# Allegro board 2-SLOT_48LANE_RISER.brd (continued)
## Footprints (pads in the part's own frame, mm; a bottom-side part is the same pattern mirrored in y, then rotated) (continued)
PCIE_X16D_H11
  round 2.413 hole 2.413 unplated: (-1.25,-11.65) (-1.25,-84.8)
  rect 1.194x1.194 hole 0.711: A1(0,0)
  round 1.194 hole 0.711: A2(2,-1) A3(0,-2) A4(2,-3) A5(0,-4) A6(2,-5) A7(0,-6) A8(2,-7) A9(0,-8) A10(2,-9) A11(0,-10) A12(2,-13) A13(0,-14) A14(2,-15) A15(0,-16) A16(2,-17) A17(0,-18) A18(2,-19) A19(0,-20) A20(2,-21) A21(0,-22) A22(2,-23) A23(0,-24) A24(2,-25) A25(0,-26) A26(2,-27) A27(0,-28) A28(2,-29) A29(0,-30) A30(2,-31) A31(0,-32) A32(2,-33) A33(0,-34) A34(2,-35) A35(0,-36) A36(2,-37) A37(0,-38) A38(2,-39) A39(0,-40) A40(2,-41) A41(0,-42) A42(2,-43) A43(0,-44) A44(2,-45) A45(0,-46) A46(2,-47) A47(0,-48) A48(2,-49) A49(0,-50) A50(2,-51) A51(0,-52) A52(2,-53) A53(0,-54) A54(2,-55) A55(0,-56) A56(2,-57) A57(0,-58) A58(2,-59) A59(0,-60) A60(2,-61) A61(0,-62) A62(2,-63) A63(0,-64) A64(2,-65) A65(0,-66) A66(2,-67) A67(0,-68) A68(2,-69) A69(0,-70) A70(2,-71) A71(0,-72) A72(2,-73) A73(0,-74) A74(2,-75) A75(0,-76) A76(2,-77) A77(0,-78) A78(2,-79) A79(0,-80) A80(2,-81) A81(0,-82) A82(2,-83) B1(-2.5,0) B2(-4.5,-1) B3(-2.5,-2) B4(-4.5,-3) B5(-2.5,-4) B6(-4.5,-5) B7(-2.5,-6) B8(-4.5,-7) B9(-2.5,-8) B10(-4.5,-9) B11(-2.5,-10) B12(-4.5,-13) B13(-2.5,-14) B14(-4.5,-15) B15(-2.5,-16) B16(-4.5,-17) B17(-2.5,-18) B18(-4.5,-19) B19(-2.5,-20) B20(-4.5,-21) B21(-2.5,-22) B22(-4.5,-23) B23(-2.5,-24) B24(-4.5,-25) B25(-2.5,-26) B26(-4.5,-27) B27(-2.5,-28) B28(-4.5,-29) B29(-2.5,-30) B30(-4.5,-31) B31(-2.5,-32) B32(-4.5,-33) B33(-2.5,-34) B34(-4.5,-35) B35(-2.5,-36) B36(-4.5,-37) B37(-2.5,-38) B38(-4.5,-39) B39(-2.5,-40) B40(-4.5,-41) B41(-2.5,-42) B42(-4.5,-43) B43(-2.5,-44) B44(-4.5,-45) B45(-2.5,-46) B46(-4.5,-47) B47(-2.5,-48) B48(-4.5,-49) B49(-2.5,-50) B50(-4.5,-51) B51(-2.5,-52) B52(-4.5,-53) B53(-2.5,-54) B54(-4.5,-55) B55(-2.5,-56) B56(-4.5,-57) B57(-2.5,-58) B58(-4.5,-59) B59(-2.5,-60) B60(-4.5,-61) B61(-2.5,-62) B62(-4.5,-63) B63(-2.5,-64) B64(-4.5,-65) B65(-2.5,-66) B66(-4.5,-67) B67(-2.5,-68) B68(-4.5,-69) B69(-2.5,-70) B70(-4.5,-71) B71(-2.5,-72) B72(-4.5,-73) B73(-2.5,-74) B74(-4.5,-75) B75(-2.5,-76) B76(-4.5,-77) B77(-2.5,-78) B78(-4.5,-79) B79(-2.5,-80) B80(-4.5,-81) B81(-2.5,-82) B82(-4.5,-83)
PQFN16_IR3823
  rect 0.305x0.66 smd: 1(-1.25,-1.78) 2(-0.75,-1.78) 3(-0.25,-1.78) 4(0.25,-1.78) 5(0.75,-1.78) 6(1.25,-1.78)
  rect 0.66x0.305 smd: 7(1.7,-1.03) 8(1.7,-0.53) 9(1.7,-0.03) 13(-1.7,-0.03) 14(-1.7,-0.53) 15(-1.7,-1.03)
  rect 0.787x1.067 smd: 10(1.69,0.92)
  rect 1.524x1.626 smd: 11(0.195,1.2)
  rect 1.321x1.626 smd: 12(-1.44,1.2)
  rect 2.438x1.422 smd: 16(0,-0.53)
PQFN17_IR3895
  rect 0.305x0.711 smd: 1(-1.95,-3.15) 2(-1.3,-3.15) 3(-0.65,-3.15) 4(0,-3.15) 5(0.65,-3.15) 6(1.3,-3.15) 7(1.95,-3.15)
  rect 0.711x0.305 smd: 8(2.45,-2.32) 9(2.45,-1.67) 10(2.45,-1.02) 14(-2.45,-1.02) 15(-2.45,-1.67) 16(-2.45,-2.32)
  custom 0.263x0.263 smd: 11(2.5,1.16)
  custom 0.533x0.533 smd: 12(0.28,2.76)
  custom 0.405x0.405 smd: 13(-2.5,1.16)
  rect 2.692x1.549 smd: 17(0,-1.66)
PQFN17_IR3899
  rect 0.254x0.762 smd: 1(-1.5,-2.425) 2(-1,-2.425) 3(-0.5,-2.425) 4(0,-2.425) 5(0.5,-2.425) 6(1,-2.425) 7(1.5,-2.425)
  rect 0.762x0.254 smd: 8(1.925,-1.645) 9(1.925,-1.145) 10(1.925,-0.645) 14(-1.925,-0.645) 15(-1.925,-1.145) 16(-1.925,-1.645)
  custom 0.2x0.2 smd: 11(1.695,1.205)
  custom 0.405x0.405 smd: 12(0.285,1.395)
  custom 0.343x0.343 smd: 13(-1.615,1.205)
  rect 2.184x1.194 smd: 17(0,-1.145)
PWR2X6D2NH_P3W3H8-9_RA
  round 3.023 hole 3.023 unplated: (-12.85,-4.32) (-2.15,-4.32)
  rect 1.549x1.549 hole 1.041: 1(0,0)
  round 1.549 hole 1.041: 2(-3,0) 3(-6,0) 4(-9,0) 5(-12,0) 6(-15,0) 7(0,3) 8(-3,3) 9(-6,3) 10(-9,3) 11(-12,3) 12(-15,3)
R0402
  rect 0.457x0.508 smd: 1(-0.4,0) 2(0.4,0)
R0603
  rect 0.813x0.711 smd: 1(-0.737,0) 2(0.737,0)
SC70-5XB
  rect 0.914x0.406 smd: 1(-1.1,0.65) 2(-1.1,0) 3(-1.1,-0.65) 4(1.1,-0.65) 5(1.1,0.65)
SOIC8
  rect 1.727x0.559 smd: 1(-2.642,1.905) 2(-2.642,0.635) 3(-2.642,-0.635) 4(-2.642,-1.905) 5(2.642,-1.905) 6(2.642,-0.635) 7(2.642,0.635) 8(2.642,1.905)
SOT23
  rect 0.914x0.813 smd: 1(-1,0.95) 2(-1,-0.95) 3(1,0)
SOT23_GDS
  rect 1.422x1.016 smd: D(1.1,0) G(-1.1,0.95) S(-1.1,-0.95)
TAJ_D_7-3X4-3
  rect 2.388x2.438 smd: 1(-3.12,0) 2(3.12,0)
TSSOP8_D65_1D2
  rect 1.168x0.61 smd: 1(-2.175,1.05) 4(-2.175,-1.05) 5(2.175,-1.05) 8(2.175,1.05)
  rect 1.168x0.432 smd: 2(-2.175,0.325) 3(-2.175,-0.325) 6(2.175,-0.325) 7(2.175,0.325)
TSSOP24_P0-65W5-6H1-2
  rect 1.6x0.305 smd: 1(-2.8,3.575) 2(-2.8,2.925) 3(-2.8,2.275) 4(-2.8,1.625) 5(-2.8,0.975) 6(-2.8,0.325) 7(-2.8,-0.325) 8(-2.8,-0.975) 9(-2.8,-1.625) 10(-2.8,-2.275) 11(-2.8,-2.925) 12(-2.8,-3.575) 13(2.8,-3.575) 14(2.8,-2.925) 15(2.8,-2.275) 16(2.8,-1.625) 17(2.8,-0.975) 18(2.8,-0.325) 19(2.8,0.325) 20(2.8,0.975) 21(2.8,1.625) 22(2.8,2.275) 23(2.8,2.925) 24(2.8,3.575)
unnamed
  round 0.991 smd: 1(0,0)
VFQFPN40_P0-4_EPAD
  custom 0.044x0.044 smd: 1(-2.45,1.8) 2(-2.45,1.4) 3(-2.45,1) 4(-2.45,0.6) 5(-2.45,0.2) 6(-2.45,-0.2) 7(-2.45,-0.6) 8(-2.45,-1) 9(-2.45,-1.4) 10(-2.45,-1.8) 11(-1.8,-2.45) 12(-1.4,-2.45) 13(-1,-2.45) 14(-0.6,-2.45) 15(-0.2,-2.45) 16(0.2,-2.45) 17(0.6,-2.45) 18(1,-2.45) 19(1.4,-2.45) 20(1.8,-2.45) 21(2.45,-1.8) 22(2.45,-1.4) 23(2.45,-1) 24(2.45,-0.6) 25(2.45,-0.2) 26(2.45,0.2) 27(2.45,0.6) 28(2.45,1) 29(2.45,1.4) 30(2.45,1.8) 31(1.8,2.45) 32(1.4,2.45) 33(1,2.45) 34(0.6,2.45) 35(0.2,2.45) 36(-0.2,2.45) 37(-0.6,2.45) 38(-1,2.45) 39(-1.4,2.45) 40(-1.8,2.45)
  rect 3.607x3.607 smd: 41(0,0)
X2QFN10_0-5_2X1-5
  rect 0.584x0.305 smd: 1(-0.638,0.75) 4(-0.638,-0.75) 6(0.638,-0.75) 9(0.638,0.75)
  rect 0.584x0.254 smd: 2(-0.638,0.25) 3(-0.638,-0.25) 7(0.638,-0.25) 8(0.638,0.25)
  rect 0.279x0.635 smd: 5(0,-0.86) 10(0,0.86)

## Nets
GND: C1.2(B) C2.2(B) C3.2(B) C4.2(B) C5.2(B) C6.2(B) C7.2(B) C8.2(B) C9.2(B) C10.2(B) C11.2(B) C12.2(B) C13.2(B) C14.2(B) C15.2(B) C16.2(B) C17.2(B) C18.2(B) C19.2(B) C20.2(B) C21.2(B) C22.2(B) C47.2(B) C48.2(B) C49.2(B) C50.2(B) C51.2(B) C52.2(B) C53.2(B) C54.2(B) C127.2(B) C128.2(B) C129.2(B) C130.2(B) C131.2(B) C132.2(B) C133.2(B) C134.2(B) C135.2(B) C136.2(B) C137.2(B) C138.2(B) C139.2(B) C140.2(B) C141.2(B) C142.2(B) C143.2(B) C144.2(B) C145.2(B) C146.2(B) C147.2(B) C148.2(B) C149.2(B) C150.2(B) C151.2(B) C152.2(B) C153.2(B) C154.2(B) C155.2(B) C156.2(B) C160.2(B) C161.2(B) C162.2(B) C163.2(B) C164.2(B) C165.2(B) C166.2(B) C167.2(B) C170.2(B) C171.2(B) C173.2(B) C174.2(B) C175.2(B) C176.2(B) C177.2(B) C178.2(B) C179.2(B) C180.2(B) C181.2(B) C182.2(B) C183.2(B) C184.2(B) C185.2(B) C186.2(B) C187.2(B) C188.2(B) C194.2(B) C215.2(B) C216.2(B) C217.2(B) C218.2(B) C219.2(B) C220.2(B) C221.2(B) C222.2(B) C223.2(B) C224.2(B) C225.2(B) C226.2(B) C227.2(B) C242.2(B) C243.2(B) C244.2(B) C245.2(B) C246.2(B) C247.2(B) C248.2(B) C249.2(B) C250.2(B) C251.2(B) C252.2(B) C253.2(B) C254.2(B) C255.2(B) C257.2(B) C258.2(B) C259.2(B) C265.2(B) C269.2(B) C271.2(B) C273.2(B) C275.2(B) C277.2(B) C279.2(B) C281.2(B) C283.2(B) C287.2(B) C290.2(B) C294.2(B) C297.2(B) C352.2(B) C386.2(B) C390.2(B) C394.2(B) C398.2(B) C402.2(B) C406.2(B) C410.2(B) C414.2(B) C418.2(B) C422.2(B) C426.2(B) C430.2(B) C434.2(B) C438.2(B) C442.2(B) C450.2(B) C451.2(B) C452.2(B) C455.2(B) C456.2(B) C460.2(B) C461.2(B) C463.2(B) C464.2(B) C465.2(B) C466.2(B) C467.2(B) C477.2(B) C478.2(B) C479.2(B) C480.2(B) CON1.4 H1.1 J1.A4 J1.A12 J1.A15 J1.A18 J1.A20 J1.A23 J1.A24 J1.A27 J1.A28 J1.A31 J1.A34 J1.A37 J1.A38 J1.A41 J1.A42 J1.A45 J1.A46 J1.A49 J1.A51 J1.A54 J1.A55 J1.A58 J1.A59 J1.A62 J1.A63 J1.A66 J1.A67 J1.A70 J1.A71 J1.A74 J1.A75 J1.A78 J1.A79 J1.A82 J1.B4 J1.B7 J1.B13 J1.B16 J1.B18 J1.B21 J1.B22 J1.B25 J1.B26 J1.B29 J1.B32 J1.B35 J1.B36 J1.B39 J1.B40 J1.B43 J1.B44 J1.B47 J1.B49 J1.B52 J1.B53 J1.B56 J1.B57 J1.B60 J1.B61 J1.B64 J1.B65 J1.B68 J1.B69 J1.B72 J1.B73 J1.B76 J1.B77 J1.B80 J2.A4 J2.A12 J2.A15 J2.A18 J2.A20 J2.A23 J2.A24 J2.A27 J2.A28 J2.A31 J2.A34 J2.A37 J2.A38 J2.A41 J2.A42 J2.A45 J2.A46 J2.A49 J2.A51 J2.A54 J2.A55 J2.A58 J2.A59 J2.A62 J2.A63 J2.A66 J2.A67 J2.A70 J2.A71 J2.A74 J2.A75 J2.A78 J2.A79 J2.A82 J2.B4 J2.B7 J2.B13 J2.B16 J2.B18 J2.B21 J2.B22 J2.B25 J2.B26 J2.B29 J2.B32 J2.B35 J2.B36 J2.B39 J2.B40 J2.B43 J2.B44 J2.B47 J2.B49 J2.B52 J2.B53 J2.B56 J2.B57 J2.B60 J2.B61 J2.B64 J2.B65 J2.B68 J2.B69 J2.B72 J2.B73 J2.B76 J2.B77 J2.B80 J5.A4 J5.A12 J5.A15 J5.A18 J5.A20 J5.A23 J5.A24 J5.A27 J5.A28 J5.A31 J5.A34 J5.A37 J5.A38 J5.A41 J5.A42 J5.A45 J5.A46 J5.A49 J5.A51 J5.A54 J5.A55 J5.A58 J5.A59 J5.A62 J5.A63 J5.A66 J5.A67 J5.A70 J5.A71 J5.A74 J5.A75 J5.A78 J5.A79 J5.A82 J5.B4 J5.B7 J5.B13 J5.B16 J5.B18 J5.B21 J5.B22 J5.B25 J5.B26 J5.B29 J5.B32 J5.B35 J5.B36 J5.B39 J5.B40 J5.B43 J5.B44 J5.B47 J5.B49 J5.B52 J5.B53 J5.B56 J5.B57 J5.B60 J5.B61 J5.B64 J5.B65 J5.B68 J5.B69 J5.B72 J5.B73 J5.B76 J5.B77 J5.B80 J6.7 J6.8 J6.9 J6.10 J6.11 J6.12 MH5.2 MH5.3 MH5.4 MH5.5 MH5.6 MH6.2 MH6.3 MH6.4 MH6.5 MH6.6 MH7.2 MH7.3 MH7.4 MH7.5 MH7.6 MH8.1 MH9.2 MH9.3 MH9.4 MH9.5 MH9.6 MH10.2 MH10.3 MH10.4 MH10.5 MH10.6 MH11.2 MH11.3 MH11.4 MH11.5 MH11.6 PC506.2(B) PC508.1 PC510.2(B) PC511.2(B) PC515.2(B) PC517.2(B) PC519.2(B) PC520.2(B) PC521.2(B) PC522.2(B) PC524.2(B) PC526.2(B) PC529.2(B) PC530.2(B) PC531.2(B) PC532.2(B) PC533.2(B) PC539.2(B) PC541.2(B) PC542.2(B) PC543.2(B) PC545.2(B) PC548.2(B) PC550.2(B) PC551.2(B) PC552.2(B) PC553.2(B) PC554.2(B) PC556.2(B) PC557.2(B) PC580.2(B) PC581.1 PC583.2(B) PC584.2(B) PC585.2(B) PC586.2(B) PC588.2(B) PC592.2(B) PC593.2(B) PC594.2(B) PC595.2(B) PC596.2(B) PC598.2(B) PC599.2(B) PC600.2(B) PC788.2(B) PC1531.2(B) PC1533.2(B) PC1588.2(B) PC1589.2(B) PC1592.2(B) PC1594.2(B) PC1595.2(B) PC1596.2(B) PC1598.2(B) PC1599.2(B) PC1600.2(B) PC2596.2(B) PR333.2(B) PR340.2(B) PR361.2(B) PR369.2(B) PR424.2(B) PR435.2(B) PR505.2(B) PU17.11 PU19.10 PU23.11 Q1.S Q2.S Q3.S Q4.S Q7.S R2.2(B) R10.2(B) R11.2(B) R12.2(B) R13.2(B) R14.2(B) R15.2(B) R16.2(B) R17.2(B) R18.2(B) R19.2(B) R20.2(B) R23.2(B) R24.2(B) R31.2(B) R32.2(B) R33.2(B) R34.2(B) R35.2(B) R36.2(B) R37.2(B) R38.2(B) R39.2(B) R40.2(B) R41.2(B) R42.2(B) R43.2(B) R58.2(B) R59.2(B) R61.2(B) R63.2(B) R65.2(B) R66.2(B) R67.2(B) R68.2(B) R71.2(B) R73.2(B) R75.2(B) R76.1 R80.2(B) R82.2(B) R84.2(B) R108.2(B) R112.2(B) R114.2(B) R116.2(B) R135.2(B) R154.2(B) R199.2(B) R200.2(B) R260.1 R275.1 R282.2(B) R284.2(B) R286.2(B) R294.2(B) R318.2(B) U1.A3 U1.A6 U1.A9 U1.A12 U1.A15 U1.A18 U1.A21 U1.AA3 U1.AA6 U1.AA9 U1.AA12 U1.AA15 U1.AB3 U1.AB6 U1.AB9 U1.AB12 U1.AB15 U1.AB18 U1.AB21 U1.AC1 U1.AC2 U1.AC3 U1.AC4 U1.AC5 U1.AC6 U1.AC7 U1.AC8 U1.AC9 U1.AC10 U1.AC11 U1.AC12 U1.AC13 U1.AC14 U1.AC15 U1.AC16 U1.AC17 U1.AC18 U1.AC19 U1.AC20 U1.AC21 U1.AC22 U1.AC23 U1.AD15 U1.AE3 U1.AE6 U1.AE9 U1.AE12 U1.AE15 U1.AE18 U1.AE21 U1.C1 U1.C2 U1.C3 U1.C4 U1.C5 U1.C6 U1.C7 U1.C8 U1.C9 U1.C10 U1.C11 U1.C12 U1.C13 U1.C14 U1.C15 U1.C16 U1.C17 U1.C18 U1.C19 U1.C20 U1.C21 U1.C22 U1.C23 U1.D3 U1.D6 U1.D9 U1.D12 U1.D15 U1.D18 U1.D21 U1.E3 U1.E6 U1.E9 U1.E12 U1.E15 U1.E18 U1.E21 U1.F6 U1.F9 U1.F12 U1.F15 U1.F18 U1.G1 U1.G2 U1.G3 U1.G4 U1.G5 U1.G6 U1.G9 U1.G12 U1.G15 U1.G18 U1.G19 U1.G20 U1.G21 U1.G22 U1.G23 U1.H3 U1.H21 U1.J3 U1.J21 U1.K1 U1.K4 U1.K5 U1.K9 U1.K11 U1.K13 U1.K15 U1.K20 U1.K21 U1.K23 U1.L3 U1.L8 U1.L10 U1.L12 U1.L14 U1.L16 U1.L21 U1.M3 U1.M9 U1.M11 U1.M13 U1.M15 U1.M21 U1.N1 U1.N4 U1.N5 U1.N8 U1.N10 U1.N12 U1.N14 U1.N16 U1.N20 U1.N21 U1.N23 U1.P3 U1.P9 U1.P11 U1.P13 U1.P15 U1.P21 U1.R3 U1.R8 U1.R10 U1.R12 U1.R14 U1.R16 U1.R21 U1.T1 U1.T4 U1.T5 U1.T9 U1.T11 U1.T13 U1.T15 U1.T20 U1.T23 U1.U3 U1.U21 U1.V3 U1.V6 U1.V9 U1.V21 U1.W1 U1.W4 U1.W9 U1.W12 U1.W17 U1.W18 U1.W19 U1.W20 U1.W21 U1.W22 U1.W23 U1.Y1 U1.Y7 U1.Y8 U1.Y9(VSS_Y9) U1.Y12 U1.Y15 U1.Y18 U1.Y21 U1.Y23 U2.12 U3.3 U4.5 U6.4 U7.4 U8.3 U9.4 U9.41 U10.6 U11.3 U12.4 U16.3 U17.3 U19.3 U20.3
GND_L: U5.3 U5.4 U5.5 U5.6 U5.7 U5.8 U5.9 U5.10 U5.11 U5.12 U25.3 U25.4 U25.5 U25.6 U25.7 U25.8 U25.9 U25.10 U25.11 U25.12 U26.3 U26.4 U26.5 U26.6 U26.7 U26.8 U26.9 U26.10 U26.11 U26.12 U29.3 U29.4 U29.5 U29.6 U29.7 U29.8 U29.9 U29.10 U29.11 U29.12 U30.3 U30.4 U30.5 U30.6 U30.7 U30.8 U30.9 U30.10 U30.11 U30.12 U33.3 U33.4 U33.5 U33.6 U33.7 U33.8 U33.9 U33.10 U33.11 U33.12 U34.3 U34.4 U34.5 U34.6 U34.7 U34.8 U34.9 U34.10 U34.11 U34.12 U37.3 U37.4 U37.5 U37.6 U37.7 U37.8 U37.9 U37.10 U37.11 U37.12 U39.3 U39.4 U39.5 U39.6 U39.7 U39.8 U39.9 U39.10 U39.11 U39.12 U41.3 U41.4 U41.5 U41.6 U41.7 U41.8 U41.9 U41.10 U41.11 U41.12 U43.3 U43.4 U43.5 U43.6 U43.7 U43.8 U43.9 U43.10 U43.11 U43.12 U45.3 U45.4 U45.5 U45.6 U45.7 U45.8 U45.9 U45.10 U45.11 U45.12
P0V9: C9.1 C16.1 C18.1 C20.1 C22.1 C145.1 C147.1 C165.1 C170.1 C173.1 C174.1 C176.1 C269.1 C271.1 C273.1 C275.1 C277.1 C279.1 C281.1 C283.1 C287.1 C290.1 C294.1 C297.1 C386.1 C394.1 C398.1 C402.1 C410.1 C414.1 C418.1 C422.1 C426.1 C430.1 C434.1 C438.1 C442.1 L3.1 L4.1 L5.1 L6.1 PC592.1 PC594.1 PC595.1 PC596.1 PC598.1 PC599.1 PC600.1 PC1592.1 PC1594.1 PC1595.1 PC1596.1 PC1598.1 PC1599.1 PC1600.1 PC2596.1 PL11.2 PR430.2(B) PR433.2(B) PR434.2(B) R148.1 U1.K8 U1.K10 U1.K12 U1.K14 U1.K16 U1.L9 U1.L11 U1.L13 U1.L15 U1.M8 U1.M10 U1.M12 U1.M14 U1.M16 U1.N9 U1.N11 U1.N13 U1.N15 U1.P8 U1.P10 U1.P12 U1.P14 U1.P16 U1.R9 U1.R11 U1.R13 U1.R15 U1.T8 U1.T10 U1.T12 U1.T14 U1.T16
P0V9_A: C2.1 C3.1 C4.1 C5.1 C6.1 C7.1 C8.1 C10.1 C11.1 C12.1 C13.1 C14.1 C15.1 C17.1 C19.1 C21.1 C141.1 C142.1 C143.1 C144.1 C146.1 C148.1 C149.1 C150.1 C151.1 C160.1 C161.1 C162.1 C163.1 C164.1 C166.1 C167.1 C171.1 C175.1 C177.1 C182.1 C183.1 C184.1 C185.1 C186.1 C187.1 C188.1 C194.1 C390.1 C406.1 L3.2 L4.2 L5.2 L6.2 U1.H6 U1.H7 U1.H8 U1.H9 U1.H12 U1.H15 U1.H16 U1.H17 U1.J7 U1.J8 U1.J9 U1.J11 U1.J13 U1.J15 U1.J16 U1.J18 U1.K6 U1.K17 U1.K18 U1.L18 U1.M7 U1.M17 U1.N7 U1.N17 U1.R6 U1.R7 U1.T6 U1.T18 U1.U8 U1.U9 U1.U11 U1.U14 U1.U15 U1.U16 U1.U17 U1.U18 U1.V12 U1.V15 U1.V16
P0V9_AGND: PC582.2(B) PR423.2(B) PR424.1 PR504.1 PU23.4 PU23.17
P0V9_COMP: PC589.1 PR427.1 PU23.3
P0V9_COMP_RC: PC591.1 PR427.2(B)
P0V9_EN: PC580.1 PR418.2(B) PU23.15
P0V9_FB: PC589.2(B) PC591.2(B) PR429.2(B) PR431.1 PR432.1 PU23.1
P0V9_FB_RC: PC597.1 PR431.2(B)
P0V9_PG: PR420.2(B) PU23.7 Q7.G R297.1
P0V9_PG_LED_H: D1.A R110.1
P0V9_PG_LED_N: D1.C Q7.D R109.2(B)
P0V9_RT: PR423.1 PU23.5
P0V9_SENSE_R_N: PR428.1 PR429.1 PR435.1 PR504.2(B) PR505.1
P0V9_SENSE_R_P: PC597.2(B) PR432.2(B) PR433.1 PR434.1
P0V9_VCC: PC581.2(B) PU23.6 PU23.10
P0V9_VIN: PC583.1 PR426.2(B) PU23.9
P0V9_VREF: PC582.1 PU23.2
P0V9_VSNS: PR428.2(B) PR430.1 PU23.8(VSNS)
P1V8: C1.1 C48.1 C50.1 C52.1 C53.1 C127.1 C129.1 C131.1 C133.1 C135.1 C137.1 C139.1 C155.1 C181.1 C451.1 L2.2 PC551.1 PC552.1 PC554.1 PC556.1 PC557.1 PL8.2 PR375.2(B) R46.1 R47.1 R48.1 R49.1 R50.1 R51.1 R52.1 R53.1 R54.1 R55.1 R56.1 R57.1 R60.1 R62.1 R64.1 R69.1 R70.1 R72.1 R74.1 R93.1 R94.1 R111.1 R113.1 R115.1 R117.1 R120.1 R121.1 R128.1 R129.1 R146.1 R277.1 R278.1 R351.1 U1.J12 U1.J17 U1.K7 U1.N6 U1.N18 U1.T7 U1.T17 U1.U12 U6.8 U11.5 U12.1
P1V8_A: C47.1 C49.1 C51.1 C54.1 C128.1 C130.1 C132.1 C134.1 C136.1 C138.1 C140.1 L2.1 U1.J10 U1.J14 U1.L7 U1.L17 U1.R17 U1.U7 U1.U10 U1.U13
P1V8_AGND: PR367.2(B) PR368.2(B) PR369.1 PR372.1 PU19.4 PU19.9 PU19.13 PU19.16
P1V8_COMP: PC547.1 PR371.1 PU19.3
P1V8_COMP_RC: PC549.1 PR371.2(B)
P1V8_EN: PC539.1 PR357.2(B) PR361.1 PU19.15
P1V8_FB: PC547.2(B) PC549.2(B) PR372.2(B) PR373.1 PR374.1 PU19.1
P1V8_FB_RC: PC555.1 PR373.2(B)
P1V8_PG: PR363.2(B) PR418.1 PU19.6 R211.2(B)
P1V8_RT: PR368.1 PU19.5
P1V8_SS: PR366.2(B) PR367.1 PU19.2
P1V8_VCC: PC541.1 PR366.1 PU19.8
P1V8_VIN: PC542.1 PR370.2(B) PU19.7
P1V8_VSENSE_R: PC555.2(B) PR374.2(B) PR375.1
P3V3: C245.1 C246.1 C247.1 C252.1 C253.1 C254.1 C450.1 C455.1 C456.1 C478.1 C480.1 CON1.1 J1.A9 J1.A10 J1.B8 J2.A9 J2.A10 J2.B8 L1.2 PC522.1 PC524.1 PC526.1 PC529.1 PC530.1 PC531.1 PC533.1 PC1531.1 PC1533.1 PL6.2 PR336.1 PR345.2(B) PR348.2(B) PR363.1 PR420.1 R3.1 R4.1 R7.1 R8.1 R77.1 R107.1 R109.1 R110.2(B) R142.1 R143.1 R147.1 R153.1 R156.1 R159.1 R160.1 R161.1 R162.1 R163.1 R191.1 R192.1 R193.1 R194.1 R203.1 R204.1 R209.1 R210.1 R296.1 R348.1 R352.1 R353.1 U12.8(VCCB) U16.5 U17.5
P3V3_AGND: PC509.2(B) PR339.2(B) PR340.1 PR343.1 PR344.1 PU17.4 PU17.17
P3V3_BUF_VDDA: C224.1 C225.1 R92.2(B) U9.1
P3V3_BUF_VDDR: C226.1 C227.1 R91.2(B) U9.5
P3V3_CLK_BUF_VDD: C215.1 C216.1 C217.1 C218.1 C219.1 C220.1 C221.1 C222.1 C257.1 C258.1 L1.1 R1.1 R91.1 R92.1 U9.12 U9.16 U9.20 U9.21 U9.25 U9.29 U9.31 U9.35 U9.39
P3V3_COMP: PC516.1 PR342.1 PU17.3
P3V3_COMP_RC: PC518.1 PR342.2(B)
P3V3_EN: PC506.1 PR332.2(B) PR333.1 PU17.15
P3V3_FB: PC516.2(B) PC518.2(B) PR344.2(B) PR346.1 PR347.1 PU17.1
P3V3_FB_RC: PC527.1 PR346.2(B)
P3V3_MB: J5.A9 J5.A10 J5.B8
P3V3_PG: PR336.2(B) PR357.1 PU17.7 R298.1
P3V3_RT: PR339.1 PU17.5
P3V3_SENSE_R: PC527.2(B) PR347.2(B) PR348.1
P3V3_STBY_MB: C178.1 C179.1 C223.1 C248.1 C255.1 C259.1 C265.1 C352.1 C452.1 C460.1 C461.1 J1.B10 J2.B10 J5.B10 R78.1 R79.1 R81.1 R83.1 R87.1 R88.1 R95.1 R96.1 R97.1 R98.1 R99.1 R100.1 R101.1 R102.1 R103.1 R104.1 R105.1 R106.1 R137.1 R141.1 R144.1 R145.1 R152.1 R185.1 R186.1 R252.1 R257.1 R258.1 R259.1 R261.1 R262.1 R263.1 R264.1 R281.1 R283.1 R285.1 R293.1 R301.1 R302.1 U2.24 U3.8(VDD) U4.1(VDD) U7.8 U8.5 U10.1(VDD) U19.5 U20.5
P3V3_VCC: PC508.2(B) PU17.6 PU17.10
P3V3_VIN: PC510.1 PR341.2(B) PU17.9
P3V3_VREF: PC509.1 PU17.2
P3V3_VSNS: PR343.2(B) PR345.1 PU17.8(VSNS)
P12V: C242.1 C243.1 C244.1 C249.1 C250.1 C251.1 C463.1 C464.1 C465.1 C477.1 C479.1 J1.A2 J1.A3 J1.B1 J1.B2 J1.B3 J2.A2 J2.A3 J2.B1 J2.B2 J2.B3 J6.1 J6.2 J6.3 J6.4 J6.5 PC532.1 PC553.1 PC593.1 PL9.2 PL12.2 PL20.2 PR332.1
P12V_MB: J5.A2 J5.A3 J5.B1 J5.B2 J5.B3
P12V_PSU: C466.1 C467.1 J6.6
85OHM_BOT_5INCH_DN: U39.1 U41.2
85OHM_BOT_5INCH_DP: U39.2 U41.1
85OHM_BOT_10INCH_DN: U43.1 U45.2
85OHM_BOT_10INCH_DP: U43.2 U45.1
85OHM_L2_5INCH_DN: U25.1 U29.2
85OHM_L2_5INCH_DP: U25.2 U29.1
85OHM_L2_10INCH_DN: U33.1 U37.2
85OHM_L2_10INCH_DP: U33.2 U37.1
85OHM_TOP_5INCH_DN: U5.1 U26.2
85OHM_TOP_5INCH_DP: U5.2 U26.1
85OHM_TOP_10INCH_DN: U30.1 U34.2
85OHM_TOP_10INCH_DP: U30.2 U34.1
AT24C64_A0: R281.2(B) R282.1 U7.1
AT24C64_A1: R283.2(B) R284.1 U7.2
AT24C64_A2: R285.2(B) R286.1 U7.3
AT24C64_WP: R293.2(B) R294.1 U7.7(WP)
CLK_100M_CPU1_PE_FG_DN: J5.A14 U9.7
CLK_100M_CPU1_PE_FG_DP: J5.A13 U9.6
CLK_100M_PEX8796_DN: R127.1 U9.24
CLK_100M_PEX8796_DP: R126.1 U9.23
CLK_100M_PEX8796_R_DN: R127.2(B) U1.W2
CLK_100M_PEX8796_R_DP: R126.2(B) U1.W3
CLK_100M_SLOT1_DN: R125.1 U9.15
CLK_100M_SLOT1_DP: R124.1 U9.14
CLK_100M_SLOT1_R_DN: J1.A14 R125.2(B)
CLK_100M_SLOT1_R_DP: J1.A13 R124.2(B)
CLK_100M_SLOT2_DN: R123.1 U9.27
CLK_100M_SLOT2_DP: R122.1 U9.26
CLK_100M_SLOT2_R_DN: J2.A14 R123.2(B)
CLK_100M_SLOT2_R_DP: J2.A13 R122.2(B)
CLK_BUF_CKPWRGD: Q4.D R4.2(B) U9.3
CLK_BUF_HIBW_BYPM_LOBW_N: R1.2(B) R2.1 U9.2
CPLD_PWRBRK_BUF_N: R154.1 U8.4(Y) U19.2 U20.2
CPLD_PWRBRK_N: J5.B30 R152.2(B) U8.2
CPLD_SLOT1_PWRBRK_N: R142.2(B) R216.1 R221.1 U20.4(Y)
CPLD_SLOT1_PWRBRK_R1_N: J1.B12 R216.2(B)
CPLD_SLOT1_PWRBRK_R2_N: J1.B30 R221.2(B)
CPLD_SLOT2_PWRBRK_N: R143.2(B) R214.1 R215.1 U19.4(Y)
CPLD_SLOT2_PWRBRK_R1_N: J2.B12 R214.2(B)
CPLD_SLOT2_PWRBRK_R2_N: J2.B30 R215.2(B)
DC_PEX8747_AA18: U1.AA18
DC_PEX8747_AA21: U1.AA21
DC_PEX8747_AD18: U1.AD18
DC_PEX8747_AD21: U1.AD21
DC_PEX8747_B9: U1.B9
DC_PEX8747_B15: U1.B15
DC_PEX8747_B21: U1.B21
DC_PEX8747_F13: U1.F13
DC_PEX8747_F16: U1.F16
DC_PEX8747_F17: U1.F17
DC_PEX8747_F20: U1.F20
DC_PEX8747_F21: U1.F21
DC_PEX8747_F23: U1.F23
DC_PEX8747_H14: U1.H14
DC_PEX8747_N22: U1.N22
DC_PEX8747_P6: U1.P6
DC_PEX8747_P7: U1.P7
DC_PEX8747_P17: U1.P17
DC_PEX8747_P18: U1.P18
DC_PEX8747_T19: U1.T19
DC_PEX8747_V8: U1.V8
DC_PEX8747_W8: U1.W8
DC_PEX8747_W13: U1.W13
DC_PEX8747_Y16: U1.Y16
DC_PEX8747_Y17: U1.Y17
DC_PEX8747_Y19: U1.Y19
DC_PEX8747_Y20: U1.Y20
DC_PEX8747_Y22: U1.Y22
EMC1412_ADDR: R302.2(B) U4.4
EMC1412_ALERT: R301.2(B) U4.6
EMC1413_ADDR: R137.2(B) U10.7
EMC1413_ALERT_N: R141.2(B) U10.8
I2C_ADDR0: R94.2(B) R108.1 U1.F5
I2C_MUX_ADD_A0: R83.2(B) R84.1 U2.1
I2C_MUX_ADD_A1: R81.2(B) R82.1 U2.2
I2C_MUX_ADD_A2: R79.2(B) R80.1 U2.21
I2C_MUX_RST_N: R78.2(B) U2.3
I2C_PCA9548_2N7002_G2_SCL: Q19.G R160.2(B)
I2C_PCA9548_2N7002_G2_SDA: Q22.G R163.2(B)
I2C_PCA9548_2N7002_G_SCL: Q20.G R161.2(B)
I2C_PCA9548_2N7002_G_SDA: Q23.G R191.2(B)
I2C_PCA9548_SC1_SLOT2_R_SCL: R22.1 U2.7
I2C_PCA9548_SC1_SLOT2_SCL: Q15.D R22.2(B) R98.2(B) R226.1
I2C_PCA9548_SC3_SLOT1_R_SCL: R26.1 U2.11
I2C_PCA9548_SC3_SLOT1_SCL: Q21.D R26.2(B) R102.2(B) R228.1
I2C_PCA9548_SC5_3V3_PE_SCL: CON1.2 Q20.S R194.2(B) R234.2(B) U12.7
I2C_PCA9548_SC5_P1V8_SCL: R277.2(B) U1.F7 U12.2
I2C_PCA9548_SC5_PE_R_SCL: R28.1 U2.16
I2C_PCA9548_SC5_PE_SCL: Q20.D R28.2(B) R104.2(B) R234.1
I2C_PCA9548_SC6_3V3_CLK_R_SCL: R90.2(B) U9.9
I2C_PCA9548_SC6_3V3_CLK_SCL: Q19.S R90.1 R193.2(B) R236.2(B)
I2C_PCA9548_SC6_CLK_R_SCL: R30.1 U2.18
I2C_PCA9548_SC6_CLK_SCL: Q19.D R30.2(B) R106.2(B) R183.1 R236.1 R280.2(B) R299.1
I2C_PCA9548_SC6_EMC1053_SCL: R183.2(B) U10.10
I2C_PCA9548_SC6_EMC1412_SCL: R299.2(B) U4.8
I2C_PCA9548_SC6_FRU_SCL: R280.1 U7.6
I2C_PCA9548_SC7_ADC128_R_SCL: R151.1 U2.20
I2C_PCA9548_SC7_ADC128_SCL_R: R157.1 U3.10
I2C_PCA9548_SC7_ADC128_SDA: R150.2(B) R158.2(B) R185.2(B)
I2C_PCA9548_SD1_SLOT2_R_SDA: R21.1 U2.6
I2C_PCA9548_SD1_SLOT2_SDA: Q18.D R21.2(B) R97.2(B) R227.1
I2C_PCA9548_SD3_SLOT1_R_SDA: R25.1 U2.10
I2C_PCA9548_SD3_SLOT1_SDA: Q24.D R25.2(B) R101.2(B) R233.1
I2C_PCA9548_SD5_3V3_PE_SDA: CON1.3 Q23.S R209.2(B) R235.2(B) U12.6
I2C_PCA9548_SD5_P1V8_SDA: R278.2(B) U1.F2 U12.3
I2C_PCA9548_SD5_PE_R_SDA: R27.1 U2.15
I2C_PCA9548_SD5_PE_SDA: Q23.D R27.2(B) R103.2(B) R235.1
I2C_PCA9548_SD6_3V3_CLK_R_SDA: R89.2(B) U9.8
I2C_PCA9548_SD6_3V3_CLK_SDA: Q22.S R89.1 R204.2(B) R237.2(B)
I2C_PCA9548_SD6_CLK_R_SDA: R29.1 U2.17
I2C_PCA9548_SD6_CLK_SDA: Q22.D R29.2(B) R105.2(B) R184.1 R237.1 R279.2(B) R300.1
I2C_PCA9548_SD6_EMC1053_SDA: R184.2(B) U10.9
I2C_PCA9548_SD6_EMC1412_SDA: R300.2(B) U4.7
I2C_PCA9548_SD6_FRU_SDA: R279.1 U7.5
I2C_PCA9548_SD7_ADC128_R_SDA: R150.1 U2.19
I2C_PCA9548_SD7_ADC128_SCL: R151.2(B) R157.2(B) R186.2(B)
I2C_PCA9548_SD7_ADC128_SDA_R: R158.1 U3.9
I2C_PE_SCL: J5.B5 R86.1
I2C_PE_SCL_R: R86.2(B) R87.2(B) U2.22
I2C_PE_SDA: J5.B6 R85.1
I2C_PE_SDA_R: R85.2(B) R88.2(B) U2.23
I2C_SLOT1_2N7002_G_SCL: Q21.G R162.2(B)
I2C_SLOT1_2N7002_G_SDA: Q24.G R192.2(B)
I2C_SLOT1_3V3_SCL: J1.B5 Q21.S R203.2(B) R228.2(B)
I2C_SLOT1_3V3_SDA: J1.B6 Q24.S R210.2(B) R233.2(B)
I2C_SLOT2_2N7002_G_SCL: Q15.G R107.2(B)
I2C_SLOT2_2N7002_G_SDA: Q18.G R153.2(B)
I2C_SLOT2_3V3_SCL: J2.B5 Q15.S R156.2(B) R226.2(B)
I2C_SLOT2_3V3_SDA: J2.B6 Q18.S R159.2(B) R227.2(B)
NC_CLK_100M_1_DN: U9.18
NC_CLK_100M_1_DP: U9.17
NC_CLK_100M_4_DN: U9.34
NC_CLK_100M_4_DP: U9.33
NC_CLK_100M_5_DN: U9.37
NC_CLK_100M_5_DP: U9.36
NC_CLK_BUF_DFBOUT_DN: U9.10
NC_CLK_BUF_DFBOUT_DP: U9.11
NC_CLK_BUF_NC: U9.30
NC_CLK_BUF_NC_1: U9.40
NC_JTAG_TCK: U1.G11
NC_JTAG_TDI: U1.J6
NC_JTAG_TDO: U1.F11
NC_JTAG_TMS: U1.H11
NC_P0V9_VP: PU23.16
NC_P3V3_VP: PU17.16
NC_PEX_FATAL_ERR_N: U1.F14
NC_PEX_INTA_N: U1.B6
PCA9617_EN: R211.1 R296.2(B) U12.5
PCIE_SLOT1_WAKE_N: J1.B11 R5.2(B)
PCIE_SLOT2_WAKE_N: J2.B11 R6.2(B)
PCIE_SLOT_PRES_N: J5.A1 R9.2(B) R132.2(B) R133.2(B) R134.2(B)
PCIE_X1_SLOT_PRES_N: J5.B17 R9.1
PCIE_X4_SLOT_PRES_N: J5.B31 R132.1
PCIE_X8_SLOT_PRES_N: J5.B48 R133.1
PCIE_X16_SLOT_PRES_N: J5.B81 R134.1
PD_JTAG_TRST_N: R10.1 U1.F3
PD_REXT_A0: R11.1 U1.W11
PD_REXT_A1: R12.1 U1.Y11
PD_REXT_A2: R13.1 U1.Y14
PD_REXT_A3: R14.1 U1.W16
PD_REXT_A4: R15.1 U1.N2
PD_REXT_A5: R16.1 U1.G7
PD_REXT_A6: R17.1 U1.F8
PD_REXT_A7: R18.1 U1.F10
PD_REXT_A8: R19.1 U1.T21
PD_REXT_A9: R20.1 U1.K22
PD_REXT_A10: R23.1 U1.G14
PD_REXT_A11: R24.1 U1.G13
PD_REXT_B0: R31.1 U1.Y10
PD_REXT_B1: R32.1 U1.V10
PD_REXT_B2: R33.1 U1.Y13
PD_REXT_B3: R34.1 U1.W15
PD_REXT_B4: R35.1 U1.W7
PD_REXT_B5: R36.1 U1.L6
PD_REXT_B6: R37.1 U1.G8
PD_REXT_B7: R38.1 U1.G10
PD_REXT_B8: R39.1 U1.T22
PD_REXT_B9: R40.1 U1.G17
PD_REXT_B10: R41.1 U1.G16
PD_REXT_B11: R42.1 U1.H13
PD_REXT_CMU: R43.1 U1.W10
PD_SLOT1_A1: J1.A1 R200.1
PD_SLOT2_A1: J2.A1 R199.1
PD_VOE_N: R76.2(B) U9.13 U9.22 U9.28
PE_CPU_RX_C_DN<0>: C35.1 U1.AB1
PE_CPU_RX_C_DN<1>: C36.1 U1.AB2
PE_CPU_RX_C_DN<2>: C37.1 U1.AB4
PE_CPU_RX_C_DN<3>: C38.1 U1.AB5
PE_CPU_RX_C_DN<4>: C91.1 U1.AB7
PE_CPU_RX_C_DN<5>: C92.1 U1.AB8
PE_CPU_RX_C_DN<6>: C93.1 U1.AB10
PE_CPU_RX_C_DN<7>: C94.1 U1.AB11
PE_CPU_RX_C_DN<8>: C95.1 U1.AB13
PE_CPU_RX_C_DN<9>: C96.1 U1.AB14
PE_CPU_RX_C_DN<10>: C97.1 U1.AB16
PE_CPU_RX_C_DN<11>: C98.1 U1.AB17
PE_CPU_RX_C_DN<12>: C99.1 U1.AB19
PE_CPU_RX_C_DN<13>: C100.1 U1.AB20
PE_CPU_RX_C_DN<14>: C101.1 U1.AB22
PE_CPU_RX_C_DN<15>: C102.1 U1.AB23
PE_CPU_RX_C_DP<0>: C23.1 U1.AA1
PE_CPU_RX_C_DP<1>: C24.1 U1.AA2
PE_CPU_RX_C_DP<2>: C25.1 U1.AA4
PE_CPU_RX_C_DP<3>: C26.1 U1.AA5
PE_CPU_RX_C_DP<4>: C79.1 U1.AA7
PE_CPU_RX_C_DP<5>: C80.1 U1.AA8
PE_CPU_RX_C_DP<6>: C81.1 U1.AA10
PE_CPU_RX_C_DP<7>: C82.1 U1.AA11
PE_CPU_RX_C_DP<8>: C83.1 U1.AA13
PE_CPU_RX_C_DP<9>: C84.1 U1.AA14
PE_CPU_RX_C_DP<10>: C85.1 U1.AA16
PE_CPU_RX_C_DP<11>: C86.1 U1.AA17
PE_CPU_RX_C_DP<12>: C87.1 U1.AA19
PE_CPU_RX_C_DP<13>: C88.1 U1.AA20
PE_CPU_RX_C_DP<14>: C89.1 U1.AA22
PE_CPU_RX_C_DP<15>: C90.1 U1.AA23
PE_CPU_RX_DN<0>: C35.2(B) J5.A17
PE_CPU_RX_DN<1>: C36.2(B) J5.A22
PE_CPU_RX_DN<2>: C37.2(B) J5.A26
PE_CPU_RX_DN<3>: C38.2(B) J5.A30
PE_CPU_RX_DN<4>: C91.2(B) J5.A36
PE_CPU_RX_DN<5>: C92.2(B) J5.A40
PE_CPU_RX_DN<6>: C93.2(B) J5.A44
PE_CPU_RX_DN<7>: C94.2(B) J5.A48
PE_CPU_RX_DN<8>: C95.2(B) J5.A53
PE_CPU_RX_DN<9>: C96.2(B) J5.A57
PE_CPU_RX_DN<10>: C97.2(B) J5.A61
PE_CPU_RX_DN<11>: C98.2(B) J5.A65
PE_CPU_RX_DN<12>: C99.2(B) J5.A69
PE_CPU_RX_DN<13>: C100.2(B) J5.A73
PE_CPU_RX_DN<14>: C101.2(B) J5.A77
PE_CPU_RX_DN<15>: C102.2(B) J5.A81
PE_CPU_RX_DP<0>: C23.2(B) J5.A16
PE_CPU_RX_DP<1>: C24.2(B) J5.A21
PE_CPU_RX_DP<2>: C25.2(B) J5.A25
PE_CPU_RX_DP<3>: C26.2(B) J5.A29
PE_CPU_RX_DP<4>: C79.2(B) J5.A35
PE_CPU_RX_DP<5>: C80.2(B) J5.A39
PE_CPU_RX_DP<6>: C81.2(B) J5.A43
PE_CPU_RX_DP<7>: C82.2(B) J5.A47
PE_CPU_RX_DP<8>: C83.2(B) J5.A52
PE_CPU_RX_DP<9>: C84.2(B) J5.A56
PE_CPU_RX_DP<10>: C85.2(B) J5.A60
PE_CPU_RX_DP<11>: C86.2(B) J5.A64
PE_CPU_RX_DP<12>: C87.2(B) J5.A68
PE_CPU_RX_DP<13>: C88.2(B) J5.A72
PE_CPU_RX_DP<14>: C89.2(B) J5.A76
PE_CPU_RX_DP<15>: C90.2(B) J5.A80
PE_CPU_TX_DN<0>: J5.B15 U1.AE1
PE_CPU_TX_DN<1>: J5.B20 U1.AE2
PE_CPU_TX_DN<2>: J5.B24 U1.AE4
PE_CPU_TX_DN<3>: J5.B28 U1.AE5
PE_CPU_TX_DN<4>: J5.B34 U1.AE7
PE_CPU_TX_DN<5>: J5.B38 U1.AE8
PE_CPU_TX_DN<6>: J5.B42 U1.AE10
PE_CPU_TX_DN<7>: J5.B46 U1.AE11
PE_CPU_TX_DN<8>: J5.B51 U1.AE13
PE_CPU_TX_DN<9>: J5.B55 U1.AE14
PE_CPU_TX_DN<10>: J5.B59 U1.AE16
PE_CPU_TX_DN<11>: J5.B63 U1.AE17
PE_CPU_TX_DN<12>: J5.B67 U1.AE19
PE_CPU_TX_DN<13>: J5.B71 U1.AE20
PE_CPU_TX_DN<14>: J5.B75 U1.AE22
PE_CPU_TX_DN<15>: J5.B79 U1.AE23
PE_CPU_TX_DP<0>: J5.B14 U1.AD1
PE_CPU_TX_DP<1>: J5.B19 U1.AD2
PE_CPU_TX_DP<2>: J5.B23 U1.AD4
PE_CPU_TX_DP<3>: J5.B27 U1.AD5
PE_CPU_TX_DP<4>: J5.B33 U1.AD7
PE_CPU_TX_DP<5>: J5.B37 U1.AD8
PE_CPU_TX_DP<6>: J5.B41 U1.AD10
PE_CPU_TX_DP<7>: J5.B45 U1.AD11
PE_CPU_TX_DP<8>: J5.B50 U1.AD13
PE_CPU_TX_DP<9>: J5.B54 U1.AD14
PE_CPU_TX_DP<10>: J5.B58 U1.AD16
PE_CPU_TX_DP<11>: J5.B62 U1.AD17
PE_CPU_TX_DP<12>: J5.B66 U1.AD19
PE_CPU_TX_DP<13>: J5.B70 U1.AD20
PE_CPU_TX_DP<14>: J5.B74 U1.AD22
PE_CPU_TX_DP<15>: J5.B78 U1.AD23
PE_SLOT1_PRES_N: J1.B81 R44.2(B)
PE_SLOT1_RX_DN<0>: J1.A17 U1.D11
PE_SLOT1_RX_DN<1>: J1.A22 U1.D10
PE_SLOT1_RX_DN<2>: J1.A26 U1.D8
PE_SLOT1_RX_DN<3>: J1.A30 U1.D7
PE_SLOT1_RX_DN<4>: J1.A36 U1.D5
PE_SLOT1_RX_DN<5>: J1.A40 U1.D4
PE_SLOT1_RX_DN<6>: J1.A44 U1.D2
PE_SLOT1_RX_DN<7>: J1.A48 U1.D1
PE_SLOT1_RX_DN<8>: J1.A53 U1.H4
PE_SLOT1_RX_DN<9>: J1.A57 U1.J4
PE_SLOT1_RX_DN<10>: J1.A61 U1.L4
PE_SLOT1_RX_DN<11>: J1.A65 U1.M4
PE_SLOT1_RX_DN<12>: J1.A69 U1.P4
PE_SLOT1_RX_DN<13>: J1.A73 U1.R4
PE_SLOT1_RX_DN<14>: J1.A77 U1.U5
PE_SLOT1_RX_DN<15>: J1.A81 U1.V5
PE_SLOT1_RX_DP<0>: J1.A16 U1.E11
PE_SLOT1_RX_DP<1>: J1.A21 U1.E10
PE_SLOT1_RX_DP<2>: J1.A25 U1.E8
PE_SLOT1_RX_DP<3>: J1.A29 U1.E7
PE_SLOT1_RX_DP<4>: J1.A35 U1.E5
PE_SLOT1_RX_DP<5>: J1.A39 U1.E4
PE_SLOT1_RX_DP<6>: J1.A43 U1.E2
PE_SLOT1_RX_DP<7>: J1.A47 U1.E1
PE_SLOT1_RX_DP<8>: J1.A52 U1.H5
PE_SLOT1_RX_DP<9>: J1.A56 U1.J5
PE_SLOT1_RX_DP<10>: J1.A60 U1.L5
PE_SLOT1_RX_DP<11>: J1.A64 U1.M5
PE_SLOT1_RX_DP<12>: J1.A68 U1.P5
PE_SLOT1_RX_DP<13>: J1.A72 U1.R5
PE_SLOT1_RX_DP<14>: J1.A76 U1.U4
PE_SLOT1_RX_DP<15>: J1.A80 U1.V4
PE_SLOT1_TX_C_DN<0>: C31.1 U1.A11
PE_SLOT1_TX_C_DN<1>: C32.1 U1.A10
PE_SLOT1_TX_C_DN<2>: C33.1 U1.A8
PE_SLOT1_TX_C_DN<3>: C34.1 U1.A7
PE_SLOT1_TX_C_DN<4>: C67.1 U1.A5
PE_SLOT1_TX_C_DN<5>: C68.1 U1.A4
PE_SLOT1_TX_C_DN<6>: C69.1 U1.A2
PE_SLOT1_TX_C_DN<7>: C70.1 U1.A1
PE_SLOT1_TX_C_DN<8>: C71.1 U1.H1
PE_SLOT1_TX_C_DN<9>: C72.1 U1.J1
PE_SLOT1_TX_C_DN<10>: C73.1 U1.L1
PE_SLOT1_TX_C_DN<11>: C74.1 U1.M1
PE_SLOT1_TX_C_DN<12>: C75.1 U1.P1
PE_SLOT1_TX_C_DN<13>: C76.1 U1.R1
PE_SLOT1_TX_C_DN<14>: C77.1 U1.U1
PE_SLOT1_TX_C_DN<15>: C78.1 U1.V1
PE_SLOT1_TX_C_DP<0>: C27.1 U1.B11
PE_SLOT1_TX_C_DP<1>: C28.1 U1.B10
PE_SLOT1_TX_C_DP<2>: C29.1 U1.B8
PE_SLOT1_TX_C_DP<3>: C30.1 U1.B7
PE_SLOT1_TX_C_DP<4>: C55.1 U1.B5
PE_SLOT1_TX_C_DP<5>: C56.1 U1.B4
PE_SLOT1_TX_C_DP<6>: C57.1 U1.B2
PE_SLOT1_TX_C_DP<7>: C58.1 U1.B1
PE_SLOT1_TX_C_DP<8>: C59.1 U1.H2
PE_SLOT1_TX_C_DP<9>: C60.1 U1.J2
PE_SLOT1_TX_C_DP<10>: C61.1 U1.L2
PE_SLOT1_TX_C_DP<11>: C62.1 U1.M2
PE_SLOT1_TX_C_DP<12>: C63.1 U1.P2
PE_SLOT1_TX_C_DP<13>: C64.1 U1.R2
PE_SLOT1_TX_C_DP<14>: C65.1 U1.U2
PE_SLOT1_TX_C_DP<15>: C66.1 U1.V2
PE_SLOT1_TX_DN<0>: C31.2(B) J1.B15
PE_SLOT1_TX_DN<1>: C32.2(B) J1.B20
PE_SLOT1_TX_DN<2>: C33.2(B) J1.B24
PE_SLOT1_TX_DN<3>: C34.2(B) J1.B28
PE_SLOT1_TX_DN<4>: C67.2(B) J1.B34
PE_SLOT1_TX_DN<5>: C68.2(B) J1.B38
PE_SLOT1_TX_DN<6>: C69.2(B) J1.B42
PE_SLOT1_TX_DN<7>: C70.2(B) J1.B46
PE_SLOT1_TX_DN<8>: C71.2(B) J1.B51
PE_SLOT1_TX_DN<9>: C72.2(B) J1.B55
PE_SLOT1_TX_DN<10>: C73.2(B) J1.B59
PE_SLOT1_TX_DN<11>: C74.2(B) J1.B63
PE_SLOT1_TX_DN<12>: C75.2(B) J1.B67
PE_SLOT1_TX_DN<13>: C76.2(B) J1.B71
PE_SLOT1_TX_DN<14>: C77.2(B) J1.B75
PE_SLOT1_TX_DN<15>: C78.2(B) J1.B79
PE_SLOT1_TX_DP<0>: C27.2(B) J1.B14
PE_SLOT1_TX_DP<1>: C28.2(B) J1.B19
PE_SLOT1_TX_DP<2>: C29.2(B) J1.B23
PE_SLOT1_TX_DP<3>: C30.2(B) J1.B27
PE_SLOT1_TX_DP<4>: C55.2(B) J1.B33
PE_SLOT1_TX_DP<5>: C56.2(B) J1.B37
PE_SLOT1_TX_DP<6>: C57.2(B) J1.B41
PE_SLOT1_TX_DP<7>: C58.2(B) J1.B45
PE_SLOT1_TX_DP<8>: C59.2(B) J1.B50
PE_SLOT1_TX_DP<9>: C60.2(B) J1.B54
PE_SLOT1_TX_DP<10>: C61.2(B) J1.B58
PE_SLOT1_TX_DP<11>: C62.2(B) J1.B62
PE_SLOT1_TX_DP<12>: C63.2(B) J1.B66
PE_SLOT1_TX_DP<13>: C64.2(B) J1.B70
PE_SLOT1_TX_DP<14>: C65.2(B) J1.B74
PE_SLOT1_TX_DP<15>: C66.2(B) J1.B78
PE_SLOT2_PRES_N: J2.B81 R45.2(B)
PE_SLOT2_RX_DN<0>: J2.A17 U1.V20
PE_SLOT2_RX_DN<1>: J2.A22 U1.U20
PE_SLOT2_RX_DN<2>: J2.A26 U1.R20
PE_SLOT2_RX_DN<3>: J2.A30 U1.P20
PE_SLOT2_RX_DN<4>: J2.A36 U1.M20
PE_SLOT2_RX_DN<5>: J2.A40 U1.L20
PE_SLOT2_RX_DN<6>: J2.A44 U1.J20
PE_SLOT2_RX_DN<7>: J2.A48 U1.H20
PE_SLOT2_RX_DN<8>: J2.A53 U1.D23
PE_SLOT2_RX_DN<9>: J2.A57 U1.D22
PE_SLOT2_RX_DN<10>: J2.A61 U1.D20
PE_SLOT2_RX_DN<11>: J2.A65 U1.D19
PE_SLOT2_RX_DN<12>: J2.A69 U1.D17
PE_SLOT2_RX_DN<13>: J2.A73 U1.D16
PE_SLOT2_RX_DN<14>: J2.A77 U1.D14
PE_SLOT2_RX_DN<15>: J2.A81 U1.D13
PE_SLOT2_RX_DP<0>: J2.A16 U1.V19
PE_SLOT2_RX_DP<1>: J2.A21 U1.U19
PE_SLOT2_RX_DP<2>: J2.A25 U1.R19
PE_SLOT2_RX_DP<3>: J2.A29 U1.P19
PE_SLOT2_RX_DP<4>: J2.A35 U1.M19
PE_SLOT2_RX_DP<5>: J2.A39 U1.L19
PE_SLOT2_RX_DP<6>: J2.A43 U1.J19
PE_SLOT2_RX_DP<7>: J2.A47 U1.H19
PE_SLOT2_RX_DP<8>: J2.A52 U1.E23
PE_SLOT2_RX_DP<9>: J2.A56 U1.E22
PE_SLOT2_RX_DP<10>: J2.A60 U1.E20
PE_SLOT2_RX_DP<11>: J2.A64 U1.E19
PE_SLOT2_RX_DP<12>: J2.A68 U1.E17
PE_SLOT2_RX_DP<13>: J2.A72 U1.E16
PE_SLOT2_RX_DP<14>: J2.A76 U1.E14
PE_SLOT2_RX_DP<15>: J2.A80 U1.E13
PE_SLOT2_TX_C_DN<0>: C43.1 U1.V23
PE_SLOT2_TX_C_DN<1>: C44.1 U1.U23
PE_SLOT2_TX_C_DN<2>: C45.1 U1.R23
PE_SLOT2_TX_C_DN<3>: C46.1 U1.P23
PE_SLOT2_TX_C_DN<4>: C115.1 U1.M23
PE_SLOT2_TX_C_DN<5>: C116.1 U1.L23
PE_SLOT2_TX_C_DN<6>: C117.1 U1.J23
PE_SLOT2_TX_C_DN<7>: C118.1 U1.H23
PE_SLOT2_TX_C_DN<8>: C119.1 U1.A23
PE_SLOT2_TX_C_DN<9>: C120.1 U1.A22
PE_SLOT2_TX_C_DN<10>: C121.1 U1.A20
PE_SLOT2_TX_C_DN<11>: C122.1 U1.A19
PE_SLOT2_TX_C_DN<12>: C123.1 U1.A17
PE_SLOT2_TX_C_DN<13>: C124.1 U1.A16
PE_SLOT2_TX_C_DN<14>: C125.1 U1.A14
PE_SLOT2_TX_C_DN<15>: C126.1 U1.A13
PE_SLOT2_TX_C_DP<0>: C39.1 U1.V22
PE_SLOT2_TX_C_DP<1>: C40.1 U1.U22
PE_SLOT2_TX_C_DP<2>: C41.1 U1.R22
PE_SLOT2_TX_C_DP<3>: C42.1 U1.P22
PE_SLOT2_TX_C_DP<4>: C103.1 U1.M22
PE_SLOT2_TX_C_DP<5>: C104.1 U1.L22
PE_SLOT2_TX_C_DP<6>: C105.1 U1.J22
PE_SLOT2_TX_C_DP<7>: C106.1 U1.H22
PE_SLOT2_TX_C_DP<8>: C107.1 U1.B23
PE_SLOT2_TX_C_DP<9>: C108.1 U1.B22
PE_SLOT2_TX_C_DP<10>: C109.1 U1.B20
PE_SLOT2_TX_C_DP<11>: C110.1 U1.B19
PE_SLOT2_TX_C_DP<12>: C111.1 U1.B17
PE_SLOT2_TX_C_DP<13>: C112.1 U1.B16
PE_SLOT2_TX_C_DP<14>: C113.1 U1.B14
PE_SLOT2_TX_C_DP<15>: C114.1 U1.B13
PE_SLOT2_TX_DN<0>: C43.2(B) J2.B15
PE_SLOT2_TX_DN<1>: C44.2(B) J2.B20
PE_SLOT2_TX_DN<2>: C45.2(B) J2.B24
PE_SLOT2_TX_DN<3>: C46.2(B) J2.B28
PE_SLOT2_TX_DN<4>: C115.2(B) J2.B34
PE_SLOT2_TX_DN<5>: C116.2(B) J2.B38
PE_SLOT2_TX_DN<6>: C117.2(B) J2.B42
PE_SLOT2_TX_DN<7>: C118.2(B) J2.B46
PE_SLOT2_TX_DN<8>: C119.2(B) J2.B51
PE_SLOT2_TX_DN<9>: C120.2(B) J2.B55
PE_SLOT2_TX_DN<10>: C121.2(B) J2.B59
PE_SLOT2_TX_DN<11>: C122.2(B) J2.B63
PE_SLOT2_TX_DN<12>: C123.2(B) J2.B67
PE_SLOT2_TX_DN<13>: C124.2(B) J2.B71
PE_SLOT2_TX_DN<14>: C125.2(B) J2.B75
PE_SLOT2_TX_DN<15>: C126.2(B) J2.B79
PE_SLOT2_TX_DP<0>: C39.2(B) J2.B14
PE_SLOT2_TX_DP<1>: C40.2(B) J2.B19
PE_SLOT2_TX_DP<2>: C41.2(B) J2.B23
PE_SLOT2_TX_DP<3>: C42.2(B) J2.B27
PE_SLOT2_TX_DP<4>: C103.2(B) J2.B33
PE_SLOT2_TX_DP<5>: C104.2(B) J2.B37
PE_SLOT2_TX_DP<6>: C105.2(B) J2.B41
PE_SLOT2_TX_DP<7>: C106.2(B) J2.B45
PE_SLOT2_TX_DP<8>: C107.2(B) J2.B50
PE_SLOT2_TX_DP<9>: C108.2(B) J2.B54
PE_SLOT2_TX_DP<10>: C109.2(B) J2.B58
PE_SLOT2_TX_DP<11>: C110.2(B) J2.B62
PE_SLOT2_TX_DP<12>: C111.2(B) J2.B66
PE_SLOT2_TX_DP<13>: C112.2(B) J2.B70
PE_SLOT2_TX_DP<14>: C113.2(B) J2.B74
PE_SLOT2_TX_DP<15>: C114.2(B) J2.B78
PE_WAKE_N: J5.B11 R5.1 R6.1
PEX8747_SPARE0: R93.2(B) U1.F1
PEX8747_SPARE1: R74.2(B) U1.Y2
PEX8747_SPARE2: R72.2(B) R73.1 U1.U6
PEX8747_SPARE3: R75.1 U1.K2
PEX_EEP_CS_N: R118.1 U1.K19
PEX_EEP_CS_R_N: R118.2(B) R128.2(B) U6.1
PEX_EEP_HOLD_N: R129.2(B) U6.7
PEX_EEP_SCLK: R130.2(B) U1.F22
PEX_EEP_SCLK_R: R130.1 U6.6
PEX_EEP_SI: R131.2(B) U1.F19
PEX_EEP_SI_R: R131.1 U6.5
PEX_EEP_SO: R119.1 U1.R18
PEX_EEP_SO_R: R119.2(B) R121.2(B) U6.2
PEX_GPIO1: R44.1 R47.2(B) U1.N3
PEX_GPIO2: R45.1 R48.2(B) U1.Y5
PEX_GPIO3: R49.2(B) U1.V11
PEX_GPIO6: R52.2(B) U1.Y6
PEX_GPIO7: R53.2(B) U1.M6
PEX_GPIO10: R56.2(B) U1.Y4
PEX_PERST_BUF_N: C154.1 C156.1 Q2.D R351.2(B) U11.2
PEX_PERST_N: U1.V7 U11.4(Y)
PEX_RORT_GOOD0_N: R46.2(B) U1.B3
PEX_RORT_GOOD4_N: R50.2(B) U1.T2
PEX_RORT_GOOD5_N: R51.2(B) U1.W6
PEX_RORT_GOOD8_N: R54.2(B) U1.T3
PEX_RORT_GOOD9_N: R55.2(B) U1.W5
PG_CKPWRGD_N: Q3.D Q4.G R3.2(B)
PG_MOS: Q3.G R297.2(B) R298.2(B)
PST_PE_SLOT1_N: J1.A11 R353.2(B) U17.4(Y)
PST_PE_SLOT2_N: J2.A11 R352.2(B) U16.4(Y)
PU_EEP_WP_R_N: R120.2(B) U6.3(WP)
PU_PCA9548_SC0: R96.2(B) U2.5
PU_PCA9548_SC2: R100.2(B) U2.9
PU_PCA9548_SC4: R145.2(B) U2.14
PU_PCA9548_SD0: R95.2(B) U2.4
PU_PCA9548_SD2: R99.2(B) U2.8
PU_PCA9548_SD4: R144.2(B) U2.13
PU_VOE1_N: R7.2(B) U9.19
PU_VOE4_N: R8.2(B) U9.32
PU_VOE5_N: R77.2(B) U9.38(VOE5*)
RST_PE_SLOT_N: J5.A11 Q1.G U16.2 U17.2
RST_PEX_MOS_N: Q1.D Q2.G R348.2(B)
SLOT1_JTAG_TCK: J1.A5 R275.2(B)
SLOT1_JTAG_TDI: J1.A6 R262.2(B)
SLOT1_JTAG_TDO: J1.A7 R263.2(B)
SLOT1_JTAG_TMS: J1.A8 R264.2(B)
SLOT1_JTAG_TRST_N: J1.B9 R261.2(B)
SLOT2_JTAG_TCK: J2.A5 R260.2(B)
SLOT2_JTAG_TDI: J2.A6 R257.2(B)
SLOT2_JTAG_TDO: J2.A7 R258.2(B)
SLOT2_JTAG_TMS: J2.A8 R259.2(B)
SLOT2_JTAG_TRST_N: J2.B9 R252.2(B)
STRAP_I2C_SMBUS_CFG_EN_N: R113.2(B) R114.1 U1.Y3
STRAP_I2C_SMBUS_EN: R111.2(B) R112.1 U1.F4
STRAP_PLL_BYPASS_N: R117.2(B) U1.V17
STRAP_RESERVED0: R70.2(B) U1.V18
STRAP_RESERVED5: R59.1 U1.AD9
STRAP_RESERVED7: R61.1 U1.K3
STRAP_RESERVED9: R65.1 U1.B18
STRAP_RESERVED14: R69.2(B) U1.AD12
STRAP_RESERVED15: R64.2(B) U1.W14
STRAP_RESERVED16: R67.1 U1.V14
STRAP_RESERVED19: R60.2(B) U1.B12
STRAP_RESERVED20: R318.1 U1.AD6
STRAP_RESERVED21: R71.1 U1.AD3
STRAP_STN1_PORTCFG0: R62.2(B) R63.1 U1.H10
STRAP_STN2_PORTCFG0: R57.2(B) R58.1 U1.N19
STRAP_TESTMODE0: R115.2(B) R116.1 U1.V13
STRAP_UP_PORTSEL0: R68.1 U1.H18
STRAP_UP_PORTSEL1: R66.1 U1.M18
THER_SEN2_DN: C260.2(B) Q25.2(E) U4.3
THER_SEN2_DP: C260.1 Q25.1 Q25.3 U4.2
THER_SEN_DN_1: C468.2(B) Q5.2(E) U10.3
THER_SEN_DN_2: C469.2(B) Q6.2(E) U10.5
THER_SEN_DP_1: C468.1 Q5.1 Q5.3 U10.2
THER_SEN_DP_2: C469.1 Q6.1 Q6.3 U10.4
TLA2024_P0V9: C153.1 R148.2(B) U3.4
TLA2024_P1V8: C152.1 R146.2(B) U3.5
TLA2024_P3V3: C180.1 R147.2(B) U3.6
TP_A19: J5.A19
TP_A32: J5.A32
TP_A33: J5.A33
TP_A50: J5.A50
TP_B12: J5.B12
TP_B82: J5.B82
TP_PCIE_X16_SLOT_JTAG_TCK: J5.A5
TP_PCIE_X16_SLOT_JTAG_TDI: J5.A6
TP_PCIE_X16_SLOT_JTAG_TDO: J5.A7
TP_PCIE_X16_SLOT_JTAG_TMS: J5.A8
TP_PE_SLOT_TRST_N: J5.B9
UNNAMED_60_RES_I55_A: R135.1 U3.1
VR_P0V9_BT: PC587.1 PU23.14
VR_P0V9_PVIN: PC584.1 PC585.1 PC586.1 PC588.1 PC788.1 PC1588.1 PC1589.1 PL20.1 PR426.1 PU23.13
VR_P0V9_SW: PC587.2(B) PL11.1 PU23.12
VR_P1V8_BT: PC546.1 PU19.14
VR_P1V8_PVIN: PC543.1 PC545.1 PC548.1 PC550.1 PL9.1 PR370.1 PU19.12
VR_P1V8_SW: PC546.2(B) PL8.1 PU19.11
VR_P3V3_BT: PC514.1 PU17.14
VR_P3V3_PVIN: PC511.1 PC515.1 PC517.1 PC519.1 PC520.1 PC521.1 PL12.1 PR341.1 PU17.13
VR_P3V3_SW: PC514.2(B) PL6.1 PU17.12

Pads without a net: J1 A19 A32 A33 A50 B17 B31 B48 B82; J2 A19 A32 A33 A50 B17 B31 B48 B82; NOREF 1; NOREF#3 1; NOREF#4 1; NOREF#7 1; NOREF#10 1; NOREF#11 1; NOREF#12 1; NOREF#13 1; NOREF#14 1; U3 2 7; U8 1; U11 1; U16 1; U17 1; U19 1; U20 1

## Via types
v1: diameter 0.762, hole 0.381, TOP to BOTTOM, 17 vias
v2: diameter 0.508, hole 0.254, TOP to BOTTOM, 2472 vias
v3: diameter 0.66, hole 0.33, TOP to BOTTOM, 2 vias
v4: diameter 0.762, hole 0.254, TOP to BOTTOM, 13 vias
v5: diameter 0.457, hole 0.254, TOP to BOTTOM, 407 vias
v6: diameter 0.635, hole 0.318, TOP to BOTTOM, 56 vias
v7: diameter 0.483, hole 0.254, TOP to BOTTOM, 11 vias
v8: diameter 0.406, hole 0.203, TOP to BOTTOM, 132 vias

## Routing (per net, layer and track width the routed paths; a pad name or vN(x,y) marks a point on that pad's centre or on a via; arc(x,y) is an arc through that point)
GND: length 599.8
  TOP w0.178: 300.11,56.32 U9.4 300.11,55.63 299.85,55.37 v2(299.85,55.07)
  TOP w0.203: C281.2 v5(129.69,83.56) ; C277.2 v5(132.09,83.56) C290.2 ; C442.2 v5(128.89,84.36) ; C142.2 v5(133.69,80.36) ; C138.2 v5(133.69,90.76) ; C390.2 v5(128.89,88.36) ; 135.78,80.95 v5(136.09,81.16) ; C430.2 v5(130.49,85.96) C394.2 ; C19.2 v5(134.49,82.76) ; v5(130.49,81.96) 130.61,81.84 C163.2 ; C130.2 v5(126.49,83.56) ; C21.2 v5(136.09,83.56) ; C151.2 v5(136.89,91.56) ; C139.2 v5(127.29,90.76) C162.2 ; v5(133.69,83.56) C10.2 ; C161.2 v5(136.89,89.96) ; C9.2 v5(128.89,89.96) ; C402.2 v5(132.09,87.56) ; C14.2 v5(133.69,85.16) ; C418.2 v5(132.09,85.16) C294.2 ; C283.2 v5(130.49,88.36) C269.2 ; v5(126.49,81.16) 126.72,81.39 C128.2 ; 128.68,91.25 v5(128.89,91.56) ; C414.2 v5(133.69,87.56) ; C271.2 v5(130.49,84.36) C297.2 ; C426.2 v5(129.69,87.56) ; C7.2 v5(128.09,89.16) ; C150.2 v5(125.69,82.76) ; C132.2 v5(132.89,82.76) ; C131.2 130,91.25 v5(130.49,90.76) C406.2 ; C438.2 v5(132.89,89.96) ; C275.2 v5(132.89,88.36) ; C141.2 v5(136.09,85.96) ; C134.2 v5(128.09,87.56) ; C22.2 v5(130.49,89.96) C16.2 ; C15.2 v5(128.09,83.56) ; C164.2 v5(129.69,81.16) ; 134.7,91.25 v5(134.49,91.56) ; 126,86.97 v5(125.69,86.76) ; C146.2 v5(135.29,89.16) ; C133.2 v5(134.49,81.96) ; C410.2 v5(132.09,89.16) ; C20.2 v5(133.69,89.16) ; C398.2 v5(129.69,89.16) ; C279.2 v5(129.69,85.16) ; C2.2 v5(125.69,89.16) ; C422.2 v5(128.89,85.96) ; C53.2 v5(130.49,79.56) ; C144.2 v5(134.49,89.96) ; C135.2 v5(128.09,80.36) ; 128.3,92.05 v5(128.09,92.36) ; C273.2 v5(130.49,82.76) C287.2 ; C18.2 v5(132.89,84.36) ; C17.2 v5(126.49,89.96) ; 126.8,84.95 v5(126.49,85.16) ; C434.2 v5(132.89,85.96)
  TOP w0.254: C3.2 135.21,100.84 v2(135.08,100.97) ; v5(128.09,85.96) 127.79,86.26 C129.2 ; v5(141.1,83.9) 141.32,83.9 ; 141.32,83.9 141.7,83.51 R38.2 141.7,83.12 R37.2 141.7,81.87 v5(141.3,81.47) 141.7,81.07 R17.2 ; 141.32,83.9 141.39,83.9 141.7,84.21 R18.2 ; v5(140.89,85.96) 142.49,85.96 R42.2 ; C54.2 v2(117.35,98.17) ; v5(134.49,78.76) 134.5,78.74 134.5,77.88 R61.2 ; R66.2 132.67,95.78 v5(132.89,95.56) 133.12,95.79 R20.2 ; C181.2 v5(133.69,87.56) ; v2(83.52,65.61) 83.52,65.17 PR435.2 ; v2(204.98,79.32) 204.59,79.71 U10.6 ; C143.2 135.46,87.9 v5(135.29,88.36) ; R135.2 262.72,30.63 U3.3 ; R19.2 128.12,95.52 v5(128.09,95.56) 128.08,95.57 R39.2 ; U8.3 v2(278.81,18.86) ; v5(130.89,76.91) 130.75,77.04 R15.2 ; R41.2 141.58,91.59 v5(141.15,91.16) 141.58,90.73 R23.2 ; R58.2 130.53,94 v5(130.49,93.96) ; 134,88.57 v5(133.69,88.36) ; R16.2 141.7,79.46 v7(141.38,79.14) 141.11,78.87 R10.2 ; C386.2 v5(128.89,82.76) ; v5(141.09,88.76) 141.58,89.24 R24.2 ; R68.2 136.03,94.7 v5(136.09,94.76) ; R65.2 141.58,93.08 v5(141.09,93.56) 141.58,94.04 R40.2 ; C194.2 v5(128.09,80.36)
  TOP w0.305: U2.12 v2(300.89,38.84)
  TOP w0.356: C49.2 v2(117.22,100.2) ; C50.2 v2(116.46,106.55) ; C51.2 v2(117.22,99.19) ; v2(116.33,102.11) 116.91,102.11 C47.2 116.91,101.35 v2(116.33,101.35) ; v2(283.03,66.62) 282.92,66.74 U16.3 ; U19.3 v2(281.55,85.08) ; C52.2 v2(117.6,106.55)
  TOP w0.381: R82.2 v2(308.81,42.42) ; C221.2 v2(295.1,61.03) ; C155.2 157.33,114.07 v2(157.05,114.35) ; C352.2 v2(282.29,20.92) ; C455.2 v2(280.87,71.65) ; R67.2 v2(124.79,104.14) R14.2 ; C452.2 v2(315.91,32.87) ; C223.2 v2(309.12,37.69) ; C219.2 v2(297.77,63.52) ; C244.2 v2(293.57,70.23) ; v2(162.82,115.82) 162.82,115.54 162.6,115.33 U11.3 ; v2(258.52,27.89) C152.2 ; v2(125.68,73.69) R73.2 ; PC542.2 80.41,103.92 v2(80.59,104.09) ; v2(297.38,69.95) 296.59,69.95 C242.2 296.53,70.59 v2(297.36,70.59) ; R282.2 v2(315.16,42.52) ; R200.2 v2(289.13,44.07) ; R12.2 v2(104.73,98.81) R31.2 ; R32.2 v2(103.46,98.81) R59.2 ; R76.1 v2(304.5,63.96) ; R11.2 107.77,100.46 v2(107.27,100.97) 106.76,100.46 R43.2 ; C8.2 v2(141.43,100.97) ; v2(163.91,112.78) 163.91,113.31 C154.2 ; C257.2 306.12,61.39 v2(306.27,61.54) ; R33.2 v2(110.44,98.19) ; R80.2 v2(306.96,31.98) ; v2(313.87,42.52) 313.89,42.55 R284.2 ; R63.2 143.08,84.2 v7(142.83,83.95) ; v2(130.89,109.98) 131,109.87 C1.2 ; v2(313.74,34.29) 313.89,34.14 R294.2 ; C180.2 v2(261.44,24.43) ; v2(98.38,98.93) R71.2 R114.2 ; v2(262.95,31.64) R135.2 ; C226.2 301.81,52.42 v2(301.96,52.27) ; R36.2 132.33,76.5 132.74,76.91 v5(133.29,76.91) ; R2.2 v2(298.53,52.27) ; R286.2 v2(312.62,42.52) ; C12.2 v2(144.5,100.81) ; C160.2 v2(140.03,100.97) ; R318.2 v2(101.42,100.97) ; C456.2 v2(280.89,31.01) ; C216.2 v2(295.1,59) ; v2(288.75,84.71) 288.88,84.58 R199.2 ; U17.3 v2(282.92,27.94) ; C227.2 v2(301.09,53.67) ; R34.2 v2(123.65,104.14) R13.2 ; R116.2 v2(122.51,102.11) ; R108.2 v2(135.21,73.66) ; R112.2 v2(136.22,73.66) ; PC543.2 v2(86.59,111.12) ; J5.A4 292.83,5.83 292.27,6.38 v2(292.27,7.04) ; C153.2 v2(258.47,28.91) ; C175.2 v2(90.53,77.09) ; U12.4 104.24,49.62 v2(104.39,49.77) ; C220.2 v2(295.1,56.97) ; R61.2 134.39,77.59 R75.2 ; C243.2 v2(294.59,70.23) ; C178.2 v2(264.49,24.51) ; C179.2 v2(263.48,24.49) ; C145.2 v2(140.29,73.79) ; U20.3 v2(283.53,44.56) ; C177.2 v2(90.53,76.07) ; R84.2 v2(309.96,42.42) ; C147.2 v2(141.3,73.79) ; R154.2 v2(282.29,18.13) ; R35.2 v2(102.44,100.97) ; R260.1 v2(292.56,70.21) ; C127.2 v2(121.49,104.14)
  TOP w0.457: C258.2 v2(306.15,59.13) ; C217.2 v2(305.97,56.59) ; C222.2 v2(303.22,63.96) ; C460.2 v2(286.52,85.58) ; C225.2 v2(298.26,54.67) ; C215.2 v2(306.94,55.32) ; v2(136.5,105.84) 136.98,105.36 U6.4 ; v2(139.27,106.81) 139.27,106.23 C48.2 140.29,106.23 v2(140.29,106.81) ; v2(287.05,44.2) 286.84,43.99 C255.2 ; C224.2 v2(296.25,53.54) ; C218.2 v2(300.68,64.14) ; v2(85.68,102.87) 85.34,103.21 PC541.2 ; C461.2 v2(286.51,45.07)
  TOP w0.508: v2(246.38,7.06) 246.38,6.35 245.83,5.8 J5.A49 ; J5.A54 240.83,6.53 v2(241.33,7.04) ; v2(233.33,7.04) 232.83,6.53 J5.A62 ; J5.A41 253.83,6.55 v2(254.31,7.04) ; v2(260.32,7.04) 260.83,6.53 J5.A34 ; U7.4 v2(311.35,42.55) ; v2(225.33,7.04) 224.83,6.53 J5.A70 ; J5.A74 220.83,6.55 v2(221.32,7.04) ; v2(274.34,7.04) 274.83,6.55 J5.A20 ; v2(268.31,7.04) 267.83,6.56 J5.A27 ; J5.A78 216.83,6.54 v2(217.33,7.04) ; C156.2 165.05,112.14 v2(164.92,112.01) ; v2(168.86,111.89) 169.9,111.89 Q1.S ; v2(223.33,7.04) 223.83,6.55 J5.A71 ; J5.A46 248.83,6.54 v2(248.33,7.04) ; v2(215.33,7.04) 215.83,6.55 J5.A79 ; v2(237.32,7.04) 236.83,6.55 J5.A58 ; v2(266.31,7.04) 266.83,6.52 J5.A28 ; PR424.2 v7(65.04,47.51) ; v2(243.32,7.04) 243.83,6.54 J5.A51 ; v2(252.31,7.04) 252.83,6.53 J5.A42 ; J5.A67 227.83,6.53 v2(227.32,7.04) ; C467.2 v2(15.83,86.36) ; Q7.S 306.57,22.01 v2(306.91,22.35) ; v2(229.32,7.04) 228.83,6.55 J5.A66 ; J5.A15 279.83,6.56 v2(279.3,7.09) ; J5.A31 263.83,6.56 v2(264.31,7.04) ; v2(168.86,115.32) 169.9,115.32 Q2.S ; v2(219.32,7.04) 219.83,6.53 J5.A75 ; C248.2 v2(286.84,84.71) ; Q4.S 300.52,47.74 v2(299.8,48.46) ; PR340.2 300.34,103.38 v2(300.13,103.17) ; v2(235.32,7.04) 235.83,6.53 J5.A59 ; v2(258.33,7.04) 257.83,6.54 J5.A37 ; Q3.S v2(295.42,48.8) ; J5.A38 256.83,6.54 v2(256.33,7.04) ; v2(277.37,7.04) 277.37,6.5 276.83,5.96 J5.A18 ; v2(250.33,7.04) 249.83,6.54 J5.A45 ; v2(239.33,7.04) 239.83,6.55 J5.A55 ; J5.A63 231.83,6.55 v2(231.33,7.04) ; J5.A23 271.83,6.54 v2(272.32,7.04) ; C465.2 19.38,100.71 v2(19.66,100.43) ; J5.A24 270.83,6.54 v2(270.32,7.04)
  TOP w0.762: v2(192.23,110.36) 191.64,109.78 CON1.4
  IN1 w0.254: v2(83.52,65.61) 83.67,65.76 83.67,66.53 84.15,67.01 100.26,67.01 101.7,68.45 113.08,68.45 117.04,72.42 117.04,74.45 118.41,75.82 122.26,75.82 122.27,75.81 122.68,75.81 123.04,75.44 127.89,75.44 131.09,78.64 131.09,82.51 130.84,82.76 v5(130.49,82.76)
  BOTTOM w0.254: U1.R10 v5(128.89,84.36) ; U1.R12 v5(128.89,85.96) ; U1.T4 v5(128.09,79.56) ; v5(137.69,93.96) 138.09,93.56 U1.D21 ; U1.K5 v5(133.69,80.36) 133.29,79.96 U1.K4 ; U1.F9 v5(136.89,83.56) ; U1.AE18 v5(120.89,90.76) ; U1.E12 137.29,86.36 v5(136.89,85.96) U1.F12 ; U1.N5 v5(130.49,80.36) ; U1.Y9 v5(124.89,83.56) 124.49,83.96 U1.AA9 ; U1.AE15 v5(120.89,88.36) ; U1.D18 v5(138.49,91.56) 138.89,91.16 U1.C18 ; U1.A12 v5(140.89,85.96) ; U1.N12 v5(130.49,85.96) ; U1.C15 v5(139.29,89.16) ; v2(301.86,110.49) 300.97,110.49 PR333.2 300.7,111.74 PC506.2 ; U1.AC4 122.69,79.76 122.69,79.36 122.89,79.16 U1.AC3 ; U1.L14 v5(132.89,88.36) U1.K15 ; U1.G15 135.69,88.76 v5(135.29,89.16) ; U1.T9 v5(128.09,83.56) ; U1.G22 v5(136.09,94.76) 135.69,95.16 U1.G23 ; U1.AC16 v5(123.29,89.16) U1.AC15 ; U1.N14 v5(130.49,88.36) ; U1.N10 v5(130.49,84.36) ; U1.G5 v5(136.09,80.36) ; U1.L3 v5(132.09,78.76) 131.69,79.16 U1.M3 ; U1.R8 v5(128.89,82.76) ; U1.Y1 125.29,77.56 v5(125.69,77.16) U1.W1 ; v5(139.02,76.52) 139.12,76.62 139.12,77.36 138.92,77.56 U1.C1 ; U1.A18 v5(141.15,91.16) ; U1.U3 v5(127.29,78.76) U1.V3 ; U1.C16 v5(139.29,89.96) 138.89,90.36 U1.C17 ; U1.G1 v5(136.09,77.16) ; U1.K13 v5(133.69,87.56) ; U1.N4 v5(130.49,79.56) U1.P3 129.9,78.98 129.48,78.98 129.29,79.16 U1.R3 ; U1.L12 v5(132.89,85.96) ; U1.C19 v5(139.29,92.36) 138.89,92.76 U1.C20 ; U1.K1 v5(133.29,76.91) ; U1.A15 v5(141.09,88.76) ; U1.H3 v5(134.49,78.76) U1.J3 ; U1.R16 v5(128.89,89.96) ; U1.C13 v5(139.29,87.56) 138.89,87.96 U1.C14 ; v7(141.38,79.14) 141.36,79.16 U1.A3 ; U1.K21 v5(132.89,93.96) U1.L21 ; U1.F15 v5(136.89,89.16) ; U1.G3 135.69,79.16 v5(136.09,79.56) U1.G4 ; U4.5 v2(311.19,79.72) ; U1.AA3 v5(124.09,78.76) 123.69,79.16 U1.AB3 ; U1.F18 v5(136.89,91.56) ; U1.C10 v5(139.29,84.36) U1.C9 138.74,83.81 138.74,83.31 U1.C8 ; v5(141.3,81.47) 141.21,81.56 U1.A6 ; U1.AE21 v5(120.89,93.16) ; U1.K11 v5(133.69,85.16) ; U1.P9 v5(129.69,83.56) ; U1.D12 v5(138.49,85.96) 138.89,86.36 U1.C12 ; U1.AD15 v5(121.69,88.36) ; U1.A21 v5(141.09,93.56) ; U1.AE3 v5(120.89,78.76) ; U1.E15 v5(137.69,89.16) ; PC580.2 64.95,40.02 v2(64.56,40.4) ; U1.AC6 122.76,81.69 122.76,82.23 U1.AC7 ; U1.D9 138.09,83.96 v5(137.69,83.56) U1.E9 ; U1.N8 v5(130.49,82.76) ; U1.AE9 v5(120.89,83.56) ; v5(139.29,81.96) 138.89,82.36 U1.C7 ; U1.Y12 v5(125.69,86.76) U1.W12 ; U1.AC20 122.89,92.78 122.69,92.98 122.69,93.36 U1.AC21 ; U1.J21 v5(133.69,93.16) U1.K20 ; U1.Y8 v5(124.89,82.76) ; U1.M13 v5(132.09,87.56) ; U1.W9 v5(125.69,83.56) ; U1.C22 v5(139.29,94.76) 138.89,95.16 U1.C23 ; U1.AA6 v5(124.09,81.16) 123.69,81.56 U1.AB6 ; U1.N16 v5(130.49,89.96) ; U1.N1 v5(130.89,76.91) ; U1.AC19 v5(122.49,91.56) ; U1.T13 v5(128.09,87.56) ; U1.AE6 v5(120.89,81.16) ; U1.E21 137.29,93.56 v5(136.89,93.96) ; U1.E18 v5(137.69,91.56) ; v2(98.53,79.88) C183.2 ; U1.W4 v5(125.69,79.56) ; U1.AC10 122.79,84.66 122.79,84.06 U1.AC9 ; U1.C21 138.89,93.56 v5(138.49,93.96) ; U1.T11 v5(128.09,85.16) ; U1.G18 v5(136.09,91.56) ; v5(132.89,89.96) U1.L16 v5(132.09,89.16) U1.M15 ; v5(141.1,83.9) 141.04,83.96 U1.A9 ; U1.G2 v5(136.09,77.96) ; U1.V9 v5(126.49,83.56) ; U1.L10 v5(132.89,84.36) ; U1.C11 v5(139.29,85.96) ; U1.H21 134.89,93.56 v5(134.49,93.96) ; U1.L8 v5(132.89,82.76) ; PC539.2 81.48,110.17 ; v2(98.53,70.36) C188.2 ; v5(129.69,85.16) U1.P11 ; U1.R14 v5(128.89,88.36) ; U1.K9 v5(133.69,83.56) ; U1.Y7 v5(124.89,81.96) ; U1.V6 v5(126.49,81.16) ; U1.T1 v5(128.49,76.91) ; U1.N20 v5(130.49,93.16) ; U1.D15 v5(138.49,89.16)
  BOTTOM w0.279: U1.M9 v5(132.09,83.56) ; U1.M11 v5(132.09,85.16) ; v5(128.09,89.16) U1.T15 ; U1.G12 v5(136.09,85.96) ; U1.G20 v5(136.09,93.16) 135.69,93.56 U1.G21 ; v5(129.69,87.56) U1.P13 ; v5(129.69,89.16) U1.P15 ; U1.G19 v5(136.09,92.36)
  BOTTOM w0.305: U1.AB21 v5(123.29,93.96)
  BOTTOM w0.356: U1.G6 v5(136.09,81.16) ; PR361.2 v2(79.07,105.59) ; U1.G9 v5(136.09,83.56) ; v5(132.89,95.56) U1.K23 ; v5(128.09,95.56) U1.T23
  BOTTOM w0.381: C182.2 v2(98.53,77.85) ; C259.2 v2(305.51,75.55) ; U1.AC2 v5(123.29,78.76) U1.AC3 ; U1.AA12 U1.AB12 v5(123.29,85.96) ; U1.AC23 v5(122.49,95.56) ; U1.N23 v5(130.49,95.56) ; U1.Y18 v5(124.89,90.76) ; C187.2 v2(98.53,69.34) ; J5.B13 v2(281.83,7.3) ; C265.2 v2(199.98,82.65) ; C176.2 v2(101.42,87.47) ; U1.W19 v5(125.69,92.36) ; U1.AC21 v5(122.49,93.96) U1.AC22 ; U1.C3 138.89,79.16 v5(138.49,78.76) U1.C2 ; v5(124.09,83.56) 123.69,83.96 U1.AB9 ; U1.AC5 v5(123.29,81.16) U1.AC6 ; J5.B7 289.83,5.78 290.17,6.12 290.17,6.98 v2(290.27,7.08) ; PC511.2 293.46,110.39 v2(293.25,110.6) ; U1.Y23 v5(125.69,94.76) U1.W23 ; C13.2 v2(98.53,74.42) ; C11.2 v2(98.53,73.41) ; C185.2 97.91,67.67 v2(98.02,67.56) ; U1.P21 130.09,93.56 v5(129.69,93.96) U1.R21 ; C186.2 v2(98.53,78.87) ; U1.C6 138.89,81.56 v5(138.49,81.16) ; C450.2 106.87,44.47 v2(107.08,44.26) ; U1.T5 v5(128.09,80.36) ; U1.AA15 v5(124.89,89.16) U1.Y15 ; U1.AC8 v5(123.29,83.56) U1.AC9 ; U1.E3 v5(137.69,78.76) 138.09,79.16 U1.D3 ; PR369.2 79.57,105.09 v2(79.07,105.59) ; U1.C5 v5(138.49,81.16) ; v5(138.49,81.16) U1.D6 ; U1.AC1 122.46,77.13 v5(122.46,76.27) ; U1.AC12 122.89,86.36 v5(123.29,85.96) ; U1.W18 v5(125.69,90.76) U1.W17 ; v5(139.29,79.56) 138.89,79.96 U1.C4 ; U1.W20 v5(125.69,93.16) 126.09,93.56 U1.W21 ; U1.E6 v5(137.69,81.16) ; v2(72.23,40.21) PC584.2 ; U1.V21 v5(127.29,93.96) U1.U21 ; U1.AC13 v5(122.49,87.56) U1.AC14 ; v5(123.29,85.96) U1.AC11 ; C451.2 107.08,47.99 v2(107.17,48.08) ; U1.T20 v5(128.09,93.16) ; C174.2 v2(100.39,81.81) ; U1.Y21 v5(125.69,93.96) U1.W22 ; U1.AC18 v5(123.29,91.56) U1.AB18 ; U1.AC17 v5(122.49,90.76) ; C184.2 v2(98.53,75.44) ; C149.2 v2(98.53,71.37) ; U1.AE12 v2(120.63,86.36) ; PC592.2 v2(89.1,41.94) ; U1.F6 v5(136.89,81.16) ; U1.M21 U1.N21 v5(130.49,93.96) ; U1.AB15 v5(124.09,89.16)
  BOTTOM w0.457: v2(299.8,99.87) PC510.2 ; PC581.1 71.45,50.42 v2(72.18,50.42) ; v2(294.52,100.38) 295.2,100.38 PC508.1 ; v2(66.24,50.26) PC583.2
  BOTTOM w0.508: J5.B76 218.83,6.55 v2(219.32,7.04) ; J5.B52 242.83,6.54 v2(243.32,7.04) ; J5.B35 259.83,6.55 v2(260.32,7.04) ; J5.B65 229.83,6.53 v2(229.32,7.04) ; J5.B32 262.83,6.53 v2(262.32,7.04) ; J5.B73 221.83,6.53 v2(221.32,7.04) ; J5.B44 250.83,6.54 v2(250.33,7.04) ; v2(272.32,7.04) 272.83,6.54 J5.B22 ; J5.B60 234.83,6.55 v2(235.32,7.04) ; J5.B69 225.83,6.55 v2(225.33,7.04) ; J5.B77 217.83,6.55 v2(217.33,7.04) ; v2(279.3,7.09) 278.83,6.61 J5.B16 ; J5.A49 245.83,5.8 246.38,6.35 v2(246.38,7.06) ; J5.B68 226.83,6.55 v2(227.32,7.04) ; J5.B53 241.83,6.55 v2(241.33,7.04) ; J5.B61 233.83,6.55 v2(233.33,7.04) ; J5.B25 269.83,6.54 v2(270.32,7.04) ; v2(231.33,7.04) 230.83,6.53 J5.B64 ; v2(248.33,7.04) 247.83,6.54 J5.B47 ; J5.B29 265.83,6.56 v2(266.31,7.04) ; J5.B80 214.83,6.54 v2(215.33,7.04) ; J5.B26 268.83,6.52 v2(268.31,7.04) ; v2(276.34,7.04) 276.83,6.55 J5.A18 ; J5.B39 255.83,6.54 v2(256.33,7.04) ; v2(258.33,7.04) 258.83,6.54 J5.B36 ; J5.A4 292.83,5.93 292.27,6.48 v2(292.27,7.04) ; J5.B43 251.83,6.55 v2(252.31,7.04) ; J5.B21 273.83,6.53 v2(274.34,7.04) ; v2(254.31,7.04) 254.83,6.53 J5.B40 ; J5.B56 238.83,6.53 v2(239.33,7.04) ; v2(237.32,7.04) 237.83,6.53 J5.B57 ; J5.B72 222.83,6.53 v2(223.33,7.04)
  vias: v1(287.13,105.51) v2(0.76,104.98) v2(0.76,99.9) v2(0.76,94.82) v2(0.76,89.74) v2(0.76,84.66) v2(0.76,79.58) v2(0.76,74.5) v2(0.76,69.42) v2(0.76,64.34) v2(0.76,59.26) v2(0.76,54.18) v2(0.76,49.1) v2(0.76,44.02) v2(0.76,38.94) v2(3.58,33.17) v2(8.66,33.17) v2(11.38,117.48) v2(13.03,102.87) v2(13.03,102.23) v2(13.03,97.41) v2(13.03,96.65) v2(13.08,90.88) v2(13.08,90.12) v2(13.74,33.17) v2(16.46,117.48) v2(18.82,33.17) v2(21.54,117.48) v2(23.9,33.17) v2(26.62,117.48) v2(28.98,33.17) v2(31.7,117.48) v2(36.78,117.48) v2(41.86,117.48) v2(42.95,33.17) v2(46.94,117.48) v2(48.03,33.17) v2(52.02,117.48) v2(53.11,33.17) v2(57.1,117.48) v2(58.19,33.17) v2(62.18,117.48) v2(63.27,33.17) v2(67.26,117.48) v2(68.35,33.17) v2(68.9,41.8) v2(68.93,41.14) v2(68.93,40.15) v2(68.93,39.46) v2(68.91,38.66) v2(71.29,48.91) v2(71.67,49.47) v2(72.05,48.89) v2(72.34,117.48) v2(72.43,49.45) v2(72.53,38.85) v2(72.53,38.19) v2(72.82,50.1) v2(72.85,48.92) v2(73.15,49.52) v2(73.43,33.17) v2(73.47,48.28) v2(73.58,50.18) v2(73.58,48.99) v2(73.91,49.6) v2(74.26,50.21) v2(74.29,49.04) v2(74.62,49.65) v2(75,50.21) v2(75.07,48.99) v2(75.35,49.65) v2(77.42,117.48) v2(78.51,33.17) v2(79.58,54.99) v2(79.58,54.23) v2(79.58,53.47) v2(79.58,52.58) v2(79.66,38.05) v2(80.52,38.05) v2(80.75,109.07) v2(82.4,60.99) v2(82.5,117.48) v2(82.45,58.75) v2(82.72,110.78) v2(82.72,109.89) v2(83.11,60.99) v2(83.11,58.75) v2(83.59,33.17) v2(84.53,104.17) v2(85.21,104.86) v2(85.21,104.17) v2(85.85,105.13) v2(85.85,104.42) v2(87.58,117.48) v2(88.67,33.17) v2(90.12,75.44) v2(90.12,74.68) v2(90.12,73.91) v2(90.12,73.15) v2(90.12,70.99) v2(90.12,70.23) v2(90.12,69.47) v2(90.12,68.83) v2(90.88,41.02) v2(91.06,108.13) v2(91.64,41.02) v2(91.74,108.13) v2(92.2,110.22) v2(92.53,41.02) v2(92.66,117.48) v2(93.42,41.02) v2(93.75,33.17) v2(95.48,109.98) v2(95.71,41.02) v2(95.86,110.62) v2(96.24,109.98) v2(96.47,41.02) v2(96.62,110.62) v2(97,109.98) v2(97.23,41.02) v2(97.49,64.39) v2(97.49,62.79) v2(97.49,61.14) v2(97.49,58.98) v2(97.49,56.82) v2(97.49,54.66) v2(97.49,52.5) v2(97.49,50.34) v2(97.74,117.48) v2(97.82,103.53) v2(97.82,102.74) v2(97.99,41.02) v2(98.12,64.39) v2(98.17,62.79) v2(98.17,61.14) v2(98.17,58.98) v2(98.17,56.82) v2(98.17,54.66) v2(98.17,52.5) v2(98.17,50.34) v2(98.53,103.53) v2(98.53,102.74) v2(98.83,33.17) v2(102.82,117.48) v2(103.91,33.17) v2(107.9,117.48) v2(108.99,33.17) v2(112.98,117.48) v2(114.07,33.17) v2(118.06,117.48) v2(119.15,33.17) v2(123.14,117.48) v2(124.23,33.17) v2(128.22,117.48) v2(129.31,33.17) v2(133.3,117.48) v2(138.38,117.48) v2(143.28,33.17) v2(143.46,117.48) v2(148.36,33.17) v2(148.54,117.48) v2(153.44,33.17) v2(153.62,117.48) v2(156.92,108.46) v2(156.92,107.57) v2(157.94,108.46) v2(157.94,107.57) v2(158.52,33.17) v2(158.7,117.48) v2(159.21,108.46) v2(159.21,107.57) v2(163.6,33.17) v2(163.78,117.48) v2(168.86,117.48) v2(169.1,32.25) v2(169.81,26.85) v2(169.81,16) v2(173.36,14.67) v2(173.94,117.48) v2(178.44,14.67) v2(179.02,117.48) v2(183.52,14.67) v2(184.1,117.48) v2(188.6,14.67) v2(189.18,117.48) v2(193.68,14.67) v2(194.01,82.5) v2(194.26,117.48) v2(199.19,13.93) v2(199.34,117.48) v2(201.37,106.3) v2(203.66,44.83) v2(204.29,106.43) v2(204.42,117.48) v2(204.49,12.19) v2(209.5,117.48) v2(209.95,11.18) v2(213.33,9.78) v2(213.61,7.04) v2(214.58,117.48) v2(219.66,117.48) v2(224.74,117.48) v2(229.82,117.48) v2(234.9,117.48) v2(239.98,117.48) v2(245.06,117.48) v2(245.32,7.04) v2(250.14,117.48) v2(255.22,117.48) v2(260.3,117.48) v2(265.38,117.48) v2(267.65,29.66) v2(270.46,117.48) v2(274.92,31.06) v2(275.38,106.46) v2(275.38,104.23) v2(275.38,101.99) v2(275.54,117.48) v2(276.07,106.46) v2(276.07,104.23) v2(276.07,101.99) v2(276.67,31.06) v2(279.71,24.26) v2(280.32,113.07) v2(280.62,117.48) v2(281.03,113.07) v2(281.8,112.78) v2(281.79,110.46) v2(281.81,108.95) v2(281.81,108.29) v2(281.76,12.57) v2(281.86,109.71) v2(283.01,8.56) v2(283.22,107.22) v2(283.22,106.26) v2(283.24,105.19) v2(283.24,104.12) v2(283.24,103.16) v2(283.24,102.09) v2(283.54,12.57) v2(284.15,69.34) v2(284.43,28.57) v2(285.07,69.34) v2(285.7,117.48) v2(286.08,29.08) v2(286.06,7.06) v2(286.21,69.72) v2(287.35,29.41) v2(287.48,70.23) v2(288.37,29.41) v2(288.49,70.23) v2(288.6,113.04) v2(288.6,112.38) v2(288.62,24.38) v2(289.21,68.45) v2(290.78,117.48) v2(290.76,108.97) v2(290.76,108.19) v2(290.84,101.48) v2(291.12,102.09) v2(291.06,28.83) v2(291.22,100.95) v2(291.54,83.95) v2(291.54,83.19) v2(291.54,43.31) v2(291.54,42.55) v2(291.57,101.48) v2(291.8,102.08) v2(291.95,100.95) v2(292.11,102.66) v2(292.26,101.53) v2(292.43,29.59) v2(292.61,102.09) v2(292.64,101) v2(292.74,102.82) v2(293.02,101.53) v2(293.22,68.33) v2(293.38,102.07) v2(293.43,100.94) v2(293.45,29.59) v2(293.68,112.81) v2(293.68,112.15) v2(293.78,101.56) v2(294.16,102.07) v2(294.27,101.12) v2(294.46,29.59) v2(294.87,26.52) v2(295.86,117.48) v2(295.89,7.98) v2(296.52,12.19) v2(297.29,112.18) v2(297.29,111.54) v2(297.29,110.86) v2(297.29,109.86) v2(297.31,109.2) v2(297.38,30.35) v2(297.38,29.59) v2(298.42,66.09) v2(299.29,60.15) v2(299.29,58.75) v2(299.29,57.22) v2(299.26,44.63) v2(300.16,66.09) v2(300.69,60.15) v2(300.71,58.7) v2(300.69,57.22) v2(300.81,9.17) v2(300.94,117.48) v2(300.86,44.68) v2(301.87,49.53) v2(302.09,60.15) v2(302.09,58.75) v2(302.09,57.22) v2(303.62,49.53) v2(304.67,44.17) v2(305.89,9.17) v2(306.02,117.48) v2(306.12,52.07) v2(307.27,41.58) v2(309.22,27.05) v2(309.72,54.64) v2(310.21,30.43) v2(310.97,9.17) v2(311.1,117.48) v2(311.47,54.64) v2(312.93,77.22) v2(313.13,31.88) v2(314.48,48.49) v2(314.58,79.38) v2(314.81,50.6) v2(314.89,30.02) v2(316.05,9.17) v2(316.18,117.48) v2(320.83,117.47) v2(321.29,112.17) v2(321.29,107.09) v2(321.29,102.01) v2(321.29,96.93) v2(321.29,91.85) v2(321.29,86.77) v2(321.29,81.69) v2(321.29,76.61) v2(321.29,71.53) v2(321.29,66.45) v2(321.29,61.37) v2(321.29,56.29) v2(321.29,51.21) v2(321.29,46.13) v2(321.29,41.05) v2(321.29,35.97) v2(321.29,30.89) v2(321.29,25.81) v2(321.29,20.73) v2(321.29,15.65) v2(321.29,10.57) v6(90.8,105.49) v6(275.27,101.28)
